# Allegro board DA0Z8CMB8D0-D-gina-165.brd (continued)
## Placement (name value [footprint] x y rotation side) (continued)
R462  ev@100/f_4  [RC0402]  57.79 157.32 270 bottom
R463  ev@100/f_4  [RC0402]  58.94 157.32 90 bottom
R464  *short_4  [SHORT0402]  149.95 156.83 0 bottom
R465  ev@1.33k/f_4  [RC0402]  31 156.68 180 bottom
R466  ev@243_4  [RC0402]  56.65 155.16 270 bottom
R467  22/j_4  [RC0402]  109.94 154.67 0 bottom
R468  ev@10k/f_4  [RC0402]  69.94 154.54 90 bottom
R469  ev@100/f_4  [RC0402]  67.32 154.52 270 bottom
R470  ev@100/f_4  [RC0402]  68.46 154.52 270 bottom
R471  ev@100/f_4  [RC0402]  64.4 153.89 0 bottom
R472  22/j_4  [RC0402]  109.94 153.65 0 bottom
R473  ev@100/f_4  [RC0402]  64.4 152.87 0 bottom
R474  2.2k_4  [RC0402]  87.33 152.64 90 bottom
R475  2.2k_4  [RC0402]  98 152.64 180 bottom
R476  *1m_4  [RC0402]  112.1 152.64 0 bottom
R477  ev@100/f_4  [RC0402]  66.05 152.24 270 bottom
R478  ev@100/f_4  [RC0402]  67.32 152.24 270 bottom
R479  ev@100/f_4  [RC0402]  68.46 152.24 270 bottom
R480  ev@100/f_4  [RC0402]  64.4 151.73 0 bottom
R481  2.2k_4  [RC0402]  98 151.62 180 bottom
R482  *1m_4  [RC0402]  112.1 151.62 0 bottom
R483  22/j_4  [RC0402]  109.94 150.61 0 bottom
R484  4.7k_4  [RC0402]  98 150.48 180 bottom
R485  ev@100/f_4  [RC0402]  64.4 150.46 0 bottom
R486  2.2k_4  [RC0402]  84.16 149.84 180 bottom
R487  ev@10k/f_4  [RC0402]  66.18 149.83 90 bottom
R488  22/j_4  [RC0402]  109.94 149.59 0 bottom
R489  10k_4  [RC0402]  98 149.34 180 bottom
R490  ev@100/f_4  [RC0402]  64.4 149.32 180 bottom
R491  100k_4  [RC0402]  143.47 149.08 180 bottom
R492  *short_4  [SHORT0402]  86.45 148.7 180 bottom
R493  ev@2.49k/f_4  [RC0402]  28.03 143.49 180 bottom
R494  *short_6  [SHORT0603]  152.36 139.81 180 bottom
R495  *0_8  [RC0805]  105.93 139.18 90 bottom
R497  *short0402  [SHORT0402]  102.07 137.78 180 bottom
R498  ev@243_4  [RC0402]  73.92 137.76 90 bottom
R499  10k_4  [RC0402]  101.81 136.64 180 bottom
R500  3.01k/f_4  [RC0402]  126.96 136.25 270 bottom
R501  1m_4  [RC0402]  129.63 135.72 180 bottom
R502  *0_4  [RC0402]  117.05 134.86 90 bottom
R503  *0_4  [RC0402]  118.07 134.86 90 bottom
R504  10k_4  [RC0402]  120.1 134.86 90 bottom
R505  10k_4  [RC0402]  121.12 134.86 90 bottom
R506  *10k_4  [RC0402]  104.35 134.48 270 bottom
R507  10k_4  [RC0402]  105.5 134.48 270 bottom
R508  10k_4  [RC0402]  101.86 134.35 0 bottom
R509  *short_4  [SHORT0402]  126.83 134.1 270 bottom
R510  3.01k/f_4  [RC0402]  127.85 134.1 270 bottom
R511  8.2k_4  [RC0402]  137.88 134.1 90 bottom
R512  *short_4  [SHORT0402]  138.9 134.1 90 bottom
R513  3.01k/f_4  [RC0402]  139.91 134.1 90 bottom
R514  2.2k_4  [RC0402]  141.94 134.1 90 bottom
R515  2.2k_4  [RC0402]  143.6 134.1 90 bottom
R516  *1k_4  [RC0402]  147.66 133.97 270 bottom
R517  *1k_4  [RC0402]  148.68 133.97 90 bottom
R518  *short0402  [SHORT0402]  97.75 133.71 270 bottom
R519  *0_4  [RC0402]  99.02 133.71 90 bottom
R520  10k_4  [RC0402]  150.17 133.59 270 bottom
R521  *0_4  [RC0402]  96.48 131.94 90 bottom
R522  100/f_4  [RC0402]  102.32 131.81 0 bottom
R523  10k_4  [RC0402]  148.17 131.56 270 bottom
R524  10k_4  [RC0402]  149.18 131.56 270 bottom
R525  10k_4  [RC0402]  150.2 131.56 270 bottom
R526  *short_4  [SHORT0402]  102.32 130.79 180 bottom
R527  10k_4  [RC0402]  148.68 129.9 180 bottom
R528  10k_4  [RC0402]  150.71 129.9 0 bottom
R529  10k_4  [RC0402]  152.74 129.9 180 bottom
R530  *short_4  [SHORT0402]  102.32 129.78 180 bottom
R531  *iv@10k_4  [RC0402]  152.74 128.89 180 bottom
R532  100/f_4  [RC0402]  102.32 128.76 0 bottom
R533  10k_4  [RC0402]  148.68 128.63 180 bottom
R534  *10k_4  [RC0402]  150.71 128.63 0 bottom
R535  *evg@10k_4  [RC0402]  152.74 127.62 0 bottom
R536  *10k_4  [RC0402]  148.68 126.86 0 bottom
R537  10k_4  [RC0402]  150.71 126.86 180 bottom
R538  10k_4  [RC0402]  154.52 126.86 90 bottom
R539  10k_4  [RC0402]  152.99 126.48 180 bottom
R540  *10k_4  [RC0402]  148.68 125.84 0 bottom
R541  10k_4  [RC0402]  150.71 125.84 180 bottom
R542  56_4  [RC0402]  102.32 125.46 180 bottom
R543  10k_4  [RC0402]  154.26 125.33 180 bottom
R544  *10k_4  [RC0402]  148.68 124.82 180 bottom
R545  10k_4  [RC0402]  150.71 124.82 180 bottom
R546  *62_4  [RC0402]  99.78 124.7 0 bottom
R547  10k_4  [RC0402]  152.61 124.7 90 bottom
R548  62_4  [RC0402]  102.32 124.32 180 bottom
R549  *10k_4  [RC0402]  155.41 124.19 0 bottom
R550  *short_4  [SHORT0402]  148.68 123.81 180 bottom
R551  10k_4  [RC0402]  150.71 123.81 180 bottom
R552  *ev@10k/f_4  [RC0402]  22.69 123.68 270 bottom
R553  ev@10k/f_4  [RC0402]  23.83 123.68 90 bottom
R554  130/f_4  [RC0402]  99.78 123.68 180 bottom
R555  *130/f_4  [RC0402]  102.32 123.17 180 bottom
R556  ev@100k_4  [RC0402]  152.99 123.17 0 bottom
R557  iv@10k_4  [RC0402]  157.06 122.79 180 bottom
R558  *short_4  [SHORT0402]  99.78 122.67 180 bottom
R559  10k_4  [RC0402]  148.68 122.67 180 bottom
R560  *10k_4  [RC0402]  155.03 122.79 180 bottom
R561  *10k_4  [RC0402]  150.71 122.54 0 bottom
R562  ev@243_4  [RC0402]  64.14 122.52 90 bottom
R563  ev@1.33k/f_4  [RC0402]  65.29 122.52 90 bottom
R564  ev@1.33k/f_4  [RC0402]  66.56 122.52 270 bottom
R565  43_4  [RC0402]  101.94 122.11 0 bottom
R566  *ev@10k/f_4  [RC0402]  22.69 121.52 270 bottom
R567  *ev@10k/f_4  [RC0402]  23.83 121.52 90 bottom
R568  *75_4  [RC0402]  99.78 121.52 180 bottom
R569  10k_4  [RC0402]  148.68 121.52 0 bottom
R570  10k_4  [RC0402]  150.88 121.52 0 bottom
R571  *1k_4  [RC0402]  156.8 121.27 270 bottom
R572  *short_4  [SHORT0402]  157.95 121.27 270 bottom
R573  *short_4  [SHORT0402]  159.22 121.27 90 bottom
R574  iv@1k_4  [RC0402]  153.76 121.52 180 bottom
R575  10k_4  [RC0402]  148.68 120.51 0 bottom
R576  10k_4  [RC0402]  150.71 120.51 180 bottom
R577  10k_4  [RC0402]  154.9 120.51 0 bottom
R578  75_4  [RC0402]  99.78 120.38 180 bottom
R579  *short_4  [SHORT0402]  101.84 120.23 180 bottom
R580  *1k_4  [RC0402]  148.68 119.49 0 bottom
R581  10k_4  [RC0402]  152.74 119.49 180 bottom
R582  10k_4  [RC0402]  154.77 119.49 180 bottom
R583  *ev@4.99k/f_4  [RC0402]  65.67 119.47 0 bottom
R584  *ev@10k/f_4  [RC0402]  67.7 119.47 180 bottom
R585  ev@4.99k/f_4  [RC0402]  69.86 119.47 180 bottom
R586  10k_4  [RC0402]  150.71 119.24 180 bottom
R587  ev@10k_4  [RC0402]  153.25 118.47 180 bottom
R588  iv@10k_4  [RC0402]  155.28 118.47 180 bottom
R589  ev@4.99k/f_4  [RC0402]  65.67 118.46 180 bottom
R590  ev@4.99k/f_4  [RC0402]  67.7 118.46 180 bottom
R591  *ev@4.99k/f_4  [RC0402]  69.86 118.46 0 bottom
R592  *100k_4  [RC0402]  148.68 118.22 180 bottom
R593  10k_4  [RC0402]  150.71 118.22 0 bottom
R594  *1k_4  [RC0402]  98.76 117.97 0 bottom
R595  *10k_4  [RC0402]  155.03 117.46 180 bottom
R596  10k_4  [RC0402]  150.71 117.08 0 bottom
R597  *short_4  [SHORT0402]  98.76 116.95 0 bottom
R598  *short_4  [SHORT0402]  148.68 116.95 180 bottom
R599  10k_4  [RC0402]  152.99 116.95 180 bottom
R600  *short_4  [SHORT0402]  155.03 116.32 180 bottom
R601  *short_4  [SHORT0402]  150.72 116.06 180 bottom
R602  *51_4  [RC0402]  98.76 115.93 180 bottom
R603  ev@10k/f_4  [RC0402]  44.28 115.43 180 bottom
R604  ev@40.2k/f_4  [RC0402]  42.25 114.92 270 bottom
R605  *ev@10k/f_4  [RC0402]  45.93 114.79 90 bottom
R606  *ev@10k/f_4  [RC0402]  47.08 114.79 90 bottom
R607  *ev@24.9k/f_4  [RC0402]  48.22 114.79 90 bottom
R608  *ev@10k/f_4  [RC0402]  49.36 114.79 90 bottom
R609  *ev@10k/f_4  [RC0402]  50.5 114.79 90 bottom
R610  *ev@10k/f_4  [RC0402]  51.65 114.79 90 bottom
R611  ev@2.2k_4  [RC0402]  53.93 114.79 90 bottom
R612  ev@2.2k_4  [RC0402]  55.08 114.79 90 bottom
R613  ev@10k/f_4  [RC0402]  56.22 114.79 90 bottom
R614  ev@2.2k_4  [RC0402]  57.36 114.79 270 bottom
R615  *0_4  [RC0402]  148.68 114.66 0 bottom
R616  *short_4  [SHORT0402]  150.71 114.56 0 bottom
R617  *short_4  [SHORT0402]  13.67 114.16 180 bottom
R618  *ev@30.1k/f_4  [RC0402]  44.28 114.16 0 bottom
R619  2.2k_4  [RC0402]  148.68 113.65 0 bottom
R620  *0_4  [RC0402]  150.71 113.55 180 bottom
R621  *short_4  [SHORT0402]  13.67 113.14 180 bottom
R622  2.2k_4  [RC0402]  154.39 113.14 0 bottom
R623  *ev@15k/f_4  [RC0402]  44.28 113.01 0 bottom
R624  ev@10k/f_4  [RC0402]  42.25 112.76 90 bottom
R625  *ev@4.99k/f_4  [RC0402]  45.93 112.63 90 bottom
R626  *ev@45.3k/f_4  [RC0402]  47.08 112.63 90 bottom
R627  ev@49.9k/f_4  [RC0402]  48.22 112.63 270 bottom
R628  *ev@45.3k/f_4  [RC0402]  49.36 112.63 90 bottom
R629  *ev@10k/f_4  [RC0402]  50.5 112.63 90 bottom
R630  *ev@10k/f_4  [RC0402]  51.65 112.63 90 bottom
R631  ev@2.2k_4  [RC0402]  53.93 112.63 90 bottom
R632  ev@2.2k_4  [RC0402]  55.08 112.63 90 bottom
R633  ev@2.2k_4  [RC0402]  56.22 112.63 270 bottom
R634  ev@10k/f_4  [RC0402]  57.36 112.63 90 bottom
R635  10k_4  [RC0402]  154.39 112.12 180 bottom
R636  10k_4  [RC0402]  154.39 110.6 270 bottom
R637  *10k_4  [RC0402]  155.41 110.6 270 bottom
R638  10k_4  [RC0402]  156.42 110.6 90 bottom
R639  200/f_4  [RC0402]  99.91 110.35 0 bottom
R640  100/f_4  [RC0402]  102.07 108.7 180 bottom
R641  *10k_4  [RC0402]  156.17 108.57 270 bottom
R642  10k_4  [RC0402]  157.18 108.57 90 bottom
R643  10k_4  [RC0402]  154.39 108.44 270 bottom
R644  *51_4  [RC0402]  102.07 107.43 180 bottom
R645  120/f_4  [RC0402]  100.54 107.17 270 bottom
R646  *10k_4  [RC0402]  154.01 106.92 0 bottom
R647  10k_4  [RC0402]  156.68 106.92 180 bottom
R648  10k_4  [RC0402]  151.22 106.66 0 bottom
R649  *short_4  [SHORT0402]  102.07 106.16 0 bottom
R650  *10k_4  [RC0402]  150.33 104.63 180 bottom
R651  10k_4  [RC0402]  152.49 104.63 180 bottom
R652  33_4  [RC0402]  142.33 104 0 bottom
R653  *0_4  [RC0402]  158.45 103.62 180 bottom
R654  49.9/f_4  [RC0402]  137.37 103.49 270 bottom
R655  10m_4  [RC0402]  150.96 102.98 90 bottom
R656  *0_4  [RC0402]  158.45 102.6 0 bottom
R657  33_4  [RC0402]  141.69 102.22 270 bottom
R658  *short_4  [SHORT0402]  142.71 102.22 270 bottom
R659  33_4  [RC0402]  143.72 102.22 270 bottom
R660  *330k_4  [RC0402]  144.74 102.22 90 bottom
R661  *0_4  [RC0402]  146.01 102.22 90 bottom
R662  *330k_4  [RC0402]  147.28 102.22 270 bottom
R663  10k_4  [RC0402]  148.29 102.22 90 bottom
R664  49.9/f_4  [RC0402]  137.5 101.96 180 bottom
R665  1m_4  [RC0402]  149.31 101.96 270 bottom
R666  *0_4  [RC0402]  158.45 101.58 180 bottom
R667  *0_4  [RC0402]  70.63 101.19 0 bottom
R668  100k_4  [RC0402]  66.13 100.82 90 bottom
R669  100k_4  [RC0402]  67.4 100.82 90 bottom
R670  *0_4  [RC0402]  53.68 100.69 90 bottom
R671  *short_4  [SHORT0402]  54.7 100.69 270 bottom
R672  *100k_4  [RC0402]  55.71 100.69 90 bottom
R673  *0_4  [RC0402]  153.76 100.57 0 bottom
R674  10k_4  [RC0402]  158.45 100.57 180 bottom
R675  *0_4  [RC0402]  70.63 100.18 0 bottom
R676  330k_4  [RC0402]  144.99 99.93 270 bottom
R677  330k_4  [RC0402]  147.02 99.93 90 bottom
R678  *short_4  [SHORT0402]  148.55 99.81 90 bottom
R679  *short_4  [SHORT0402]  149.69 99.81 270 bottom
R680  100k/f_4  [RC0402]  151.22 99.68 90 bottom
R681  *0_4  [RC0402]  152.23 99.68 90 bottom
R682  *short_4  [SHORT0402]  70.63 99.16 180 bottom
R683  *0_4  [RC0402]  153.88 98.92 0 bottom
R684  33_4  [RC0402]  140.8 98.15 270 bottom
R685  *short_4  [SHORT0402]  70.63 98.15 180 bottom
R686  *10k_4  [RC0402]  146.45 98.15 0 bottom
R687  *10k_4  [RC0402]  153.88 97.9 0 bottom
R688  10k_4  [RC0402]  146.45 97.13 0 bottom
R689  0_4  [RC0402]  149.56 96.88 90 bottom
R690  *short_4  [SHORT0402]  232.37 91.93 180 bottom
R691  *0_4  [RC0402]  213.06 91.3 180 bottom
R692  *short_4  [SHORT0402]  232.37 90.92 180 bottom
R693  *0_4  [RC0402]  213.06 90.28 180 bottom
R694  *0_4  [RC0402]  214.33 88.76 0 bottom
R695  *0_4  [RC0402]  216.62 88.63 180 bottom
R696  *0_4  [RC0402]  216.62 87.49 180 bottom
R697  10k_4  [RC0402]  180.76 84.21 180 bottom
R698  *short_8  [SHORT0805]  188.3 82.28 180 bottom
R699  10k_4  [RC0402]  185.38 82.15 0 bottom
R700  *10k_4  [RC0402]  214.21 81.64 90 bottom
R701  *short_4  [SHORT0402]  215.22 81.64 270 bottom
R702  *0_4  [RC0402]  216.24 81.64 90 bottom
R703  *0_4  [RC0402]  217.26 81.64 90 bottom
R704  0_4  [RC0402]  218.27 81.64 90 bottom
R705  1k_4  [RC0402]  185.38 80.88 0 bottom
R706  *0_4  [RC0402]  214.46 79.74 180 bottom
R707  0_4  [RC0402]  214.46 78.6 180 bottom
R708  *short_8  [SHORT0805]  38.82 74.41 90 bottom
R709  66.5/f_4  [RC0402]  132.52 72.5 0 bottom
R710  66.5/f_4  [RC0402]  134.81 72.5 180 bottom
R711  *short_4  [SHORT0402]  232.37 73.39 180 bottom
R712  *short_4  [SHORT0402]  232.37 72.37 180 bottom
R713  *short_8  [SHORT0805]  216.75 70.09 180 bottom
R716  *0_6  [RC0603]  151.09 67.04 0 bottom
R717  *0_6  [RC0603]  148.8 66.53 270 bottom
R718  *short_6  [SHORT0603]  151.08 65.83 0 bottom
R719  26.1/f_4  [RC0402]  64.47 65.64 180 bottom
R720  *10k_4  [RC0402]  153.25 65.64 90 bottom
R721  *0_6  [RC0603]  218.14 65.64 90 bottom
R722  20k/f_4  [RC0402]  129.73 65.52 270 top
R723  *short_6  [SHORT0603]  155.66 64.88 270 bottom
R724  0_4  [RC0402]  138.26 64.63 180 bottom
R725  26.1/f_4  [RC0402]  64.47 64.5 180 bottom
R726  20k/f_4  [RC0402]  128.53 64.07 270 top
R727  *short_4  [SHORT0402]  144.6 63.67 90 bottom
R728  *short_4  [SHORT0402]  145.74 63.67 90 bottom
R729  *short_4  [SHORT0402]  146.76 63.67 90 bottom
R730  *short_4  [SHORT0402]  147.78 63.67 90 bottom
R731  26.1/f_4  [RC0402]  64.47 63.36 180 bottom
R732  *0_4  [RC0402]  138.26 63.36 180 bottom
R733  *short_4  [SHORT0402]  148.79 63.29 90 bottom
R734  *short_4  [SHORT0402]  149.81 63.29 90 bottom
R735  *short_4  [SHORT0402]  151.08 63.29 90 bottom
R736  *short_4  [SHORT0402]  152.22 63.29 90 bottom
R737  *short_6  [SHORT0603]  155.15 62.98 0 bottom
R738  34.8/f_4  [RC0402]  62.19 62.47 180 bottom
R739  26.1/f_4  [RC0402]  64.47 62.34 180 bottom
R740  *0_4  [RC0402]  138.26 62.09 180 bottom
R741  *100k_4  [RC0402]  215.6 62.09 180 bottom
R742  34.8/f_4  [RC0402]  62.32 61.07 0 bottom
R743  34.8/f_4  [RC0402]  64.47 61.07 180 bottom
R744  34.8/f_4  [RC0402]  64.47 59.8 180 bottom
R745  240/f_4  [RC0402]  62.32 59.67 180 bottom
R746  34.8/f_4  [RC0402]  62.32 58.53 0 bottom
R747  34.8/f_4  [RC0402]  64.47 58.53 180 bottom
R748  *short_4  [SHORT0402]  223.99 57.77 0 bottom
R749  *gs@short_6  [SHORT0603]  220.05 57.64 0 bottom
R750  34.8/f_4  [RC0402]  62.32 57.39 0 bottom
R751  34.8/f_4  [RC0402]  64.47 57.39 180 bottom
R752  240/f_4  [RC0402]  96.22 56.75 180 bottom
R753  *short_4  [SHORT0402]  223.99 55.99 0 bottom
R754  *gs@4.7k_4  [RC0402]  220.3 55.36 180 bottom
R755  *gs@short_4  [SHORT0402]  220.3 54.34 180 bottom
R756  240/f_4  [RC0402]  80.28 54.33 180 bottom
R757  240/f_4  [RC0402]  112.61 53.83 270 bottom
R758  *short_4  [SHORT0402]  223.99 53.58 0 bottom
R759  *gs@short_4  [SHORT0402]  216.24 51.67 90 bottom
R760  *gs@4.7k_4  [RC0402]  217.38 51.67 90 bottom
R761  *gs@short_4  [SHORT0402]  218.4 51.67 90 bottom
R762  *short_4  [SHORT0402]  223.99 51.04 0 bottom
R763  *1k_4  [RC0402]  122.13 48.17 0 bottom
R764  *1k_4  [RC0402]  124.42 48.17 180 bottom
R765  *tpmi@0_4  [RC0402]  172.3 48.12 0 bottom
R766  *1k_4  [RC0402]  110.14 47.35 180 bottom
R767  tpm@0_4  [RC0402]  172.3 47.1 0 bottom
R768  *1k_4  [RC0402]  122.13 46.85 0 bottom
R769  *short_4  [SHORT0402]  160.36 46.72 0 bottom
R770  *1k_4  [RC0402]  110.14 46.08 180 bottom
R771  *1k_4  [RC0402]  122.18 45.58 180 bottom
R772  *0_4  [RC0402]  110.14 44.81 180 bottom
R773  *1k_4  [RC0402]  122.18 44.56 0 bottom
R774  *short_6  [SHORT0603]  239.61 44.56 0 bottom
R775  *20k/f_4  [RC0402]  172.3 44.05 180 bottom
R776  *0_4  [RC0402]  110.14 43.54 180 bottom
R777  *1k_4  [RC0402]  122.18 43.54 180 bottom
R778  *tpmi@4.7k  [RC0402]  172.3 43.04 0 bottom
R779  *short_4  [SHORT0402]  223.48 43.04 90 bottom
R780  *tpm@4.7k  [RC0402]  172.3 42.02 180 bottom
R781  tpm@10k_4  [RC0402]  172.3 41 0 bottom
R782  tpm@0_4  [RC0402]  160.36 40.75 0 bottom
R783  *short_4  [SHORT0402]  223.48 40.5 270 bottom
R784  *tpmi@0_4  [RC0402]  172.3 39.99 0 bottom
R785  *short_4  [SHORT0402]  160.36 39.73 0 bottom
R786  *short_4  [SHORT0402]  223.99 38.85 0 bottom
R787  tpmn@0_4  [RC0402]  160.36 38.72 0 bottom
R788  *short_4  [SHORT0402]  223.99 37.7 0 bottom
R789  *0_4  [RC0402]  235.29 26.4 0 bottom
R790  0_4  [RC0402]  224.62 88.76 270 top
R791  0_4  [RC0402]  225.64 88.76 270 top
R792  *100k_4  [RC0402]  224.49 64.75 0 bottom
R794  *68.1k/f_4  [RC0402]  80.37 74.25 180 top
R795  *4.7k_4  [RC0402]  83.27 73.24 180 top
R796  *150k/f_4  [RC0402]  80.37 75.29 0 top
R797  *4.7k_4  [RC0402]  80.37 73.24 180 top
RP1  *10k_10p8r  [10P8R]  62.44 48.75 90 top
RP2  10k_10p8r  [10P8R]  159.98 108.7 270 bottom
RV1  *5v/0.2p_4  [CC0402]  84.79 155.69 90 top
SW1  *power switch  [SW-TME-532-V-6P]  163.03 42.66 0 top
SW2  switch_1.5  [SW-TC901-AA1G-A160T-6P]  103.88 42.46 270 bottom
TP1  *  [TP2650]  104.1 164.07 0 top
TP2  *  [TP2650]  110.91 140.14 0 top
TP3  *  [TP2650]  112.18 140.14 0 top
TP4  *  [TP2650]  137.5 132.32 0 top
TP6  *  [TP2650]  137.75 130.79 0 top
TP9  *  [TP2650]  141.56 129.65 0 top
TP10  *  [TP2050]  49.39 129.4 270 top
TP11  *  [TP2050]  50.76 128.76 270 top
TP13  *  [TP2675]  52.16 127.75 270 top
TP14  *  [TP2650]  142.2 127.11 0 top
TP15  pad  [TP2650]  109.94 126.83 0 top
TP16  *  [TP2650]  106.77 126.35 0 top
TP17  *  [TP2650]  108.16 126.32 0 top
TP18  *  [TP2675]  50.12 126.22 270 top
TP19  *  [TP2650]  104.23 126.09 0 top
TP20  *  [TP2650]  105.5 126.09 0 top
TP21  *  [TP2650]  109.31 125.64 0 top
TP22  *  [TP2050]  52.92 124.82 0 top
TP23  *  [TP2650]  107.02 124.75 0 top
TP24  pad  [TP2650]  108.31 124.75 0 top
TP25  pad  [TP2650]  109.41 124.06 0 top
TP26  *  [TP2650]  146.06 124.06 0 top
TP27  pad  [TP2650]  106.59 123.43 0 top
TP28  *  [TP2650]  105.32 123.3 0 top
TP29  pad  [TP2650]  108.16 123.3 0 top
TP30  *  [TP2650]  104.1 122.95 0 top
TP31  pad  [TP2650]  109.33 122.59 0 top
TP32  *  [TP2650]  106.46 122.16 0 top
TP33  *  [TP2650]  103.59 121.78 0 top
TP34  pad  [TP2650]  108.16 121.78 0 top
TP35  *  [TP2650]  93.43 121.65 0 top
TP36  *  [TP2650]  150.53 122.34 0 top
TP37  pad  [TP2650]  109.31 121.09 0 top
TP38  *  [TP2650]  101.94 121.01 0 top
TP39  *  [TP2650]  146.52 121.52 0 top
TP40  *  [TP2650]  107.02 120.3 0 top
TP41  *  [TP2650]  108.31 120.25 0 top
TP42  *  [TP2650]  102.83 120 0 top
TP43  *  [TP2650]  145.91 120.38 0 top
TP44  *  [TP2650]  101.56 119.62 0 top
TP45  *  [TP2650]  100.16 119.49 0 top
TP46  *  [TP2650]  93.52 119.2 0 top
TP47  *  [TP2650]  106.66 118.96 0 top
TP48  *  [TP2650]  145.35 118.88 0 top
TP49  pad  [TP2650]  109.31 118.86 0 top
TP50  pad  [TP2650]  108.02 118.77 0 top
TP51  *  [TP2650]  146.74 118.02 0 top
TP52  *  [TP2650]  101.99 118.37 0 top
TP53  *  [TP2650]  104.86 118.35 0 top
TP54  pad  [TP2650]  98.59 117.79 0 top
TP55  *  [TP2650]  106.38 117.66 0 top
TP56  pad  [TP2650]  109.31 117.36 0 top
TP57  pad  [TP2650]  108.04 117.31 0 top
TP58  pad  [TP2650]  126.79 117.15 0 top
TP59  pad  [TP2650]  128.02 116.82 0 top
TP60  *  [TP2650]  146.14 116.7 0 top
TP61  *  [TP2650]  144.74 116.44 0 top
TP62  *  [TP2650]  98.56 116.21 0 top
TP63  *  [TP2650]  104.86 116.19 0 top
TP64  *  [TP2650]  99.91 116.06 0 top
TP65  *  [TP2650]  88.35 115.93 0 top
TP66  pad  [TP2650]  126.07 115.93 0 top
TP67  *  [TP2650]  139.91 115.93 0 top
TP68  *  [TP2650]  101.18 115.68 0 top
TP69  *  [TP2650]  94.45 115.43 0 top
TP70  *  [TP2650]  146.52 115.43 0 top
TP71  pad  [TP2650]  109.89 115.4 0 top
TP72  pad  [TP2650]  106.64 115.3 0 top
TP73  pad  [TP2650]  108.29 115.3 0 top
TP74  *  [TP2650]  144.61 115.17 0 top
TP75  pad  [TP2650]  107.43 114.28 0 top
TP76  *  [TP2650]  144.87 113.52 0 top
TP77  *  [TP2650]  146.39 113.52 0 top
TP78  *  [TP2650]  126.35 113.12 0 top
TP79  *  [TP2650]  143.21 112.73 0 top
TP80  *  [TP2650]  126.35 111.24 0 top
TP81  *  [TP2650]  146.21 106.59 0 top
TP82  *  [TP2650]  145.25 108.95 0 top
TP83  *  [TP2650]  143.21 108.82 0 top
TP84  *  [TP2650]  86.28 105.63 0 top
TP85  *  [TP2650]  35.39 102.98 0 top
TP86  *  [TP2650]  87 93.99 0 top
TP87  *  [TP2650]  84.46 89.16 0 top
TP88  *  [TP2650]  153.88 83.93 0 top
TP89  *  [TP2650]  155.15 83.93 0 top
TP90  *pad  [TP2650]  221.95 80.88 0 top
TP91  *pad  [TP2650]  225.26 80.76 0 top
TP92  *pad  [TP2650]  216.62 79.36 270 top
TP93  *pad  [TP2650]  216.62 78.09 270 top
TP94  *pad  [TP2650]  216.62 76.69 270 top
TP95  *  [TP2650]  158.71 67.17 0 top
TP96  *  [TP2650]  158.71 65.9 0 top
TP97  *  [TP2650]  137.25 56.17 0 top
TP98  *  [TP2650]  141.94 50.28 0 top
TP99  *  [TP2650]  157.82 44.56 0 top
TP100  *  [TP2650]  168.87 40.75 0 top
TP101  *  [TP2650]  240.12 34.4 0 top
TP102  *  [TP2650]  240.12 33 0 top
TP103  *pad  [TP2675]  96.48 155.56 180 bottom
TP104  *pad  [TP2675]  96.48 150.73 180 bottom
TP105  *pad  [TP2675]  105.37 147.43 180 bottom
TP106  *  [TP2650]  116.14 138.06 180 bottom
TP107  *  [TP2650]  117.43 138.03 180 bottom
TP108  *  [TP2650]  112.73 135.62 180 bottom
TP109  *  [TP2650]  114.13 135.62 180 bottom
TP110  pad  [TP2650]  145.3 135.37 180 bottom
TP111  pad  [TP2650]  146.64 135.37 180 bottom
TP112  pad  [TP2650]  103.34 134.98 180 bottom
TP113  *  [TP2650]  109.94 134.35 180 bottom
TP114  *  [TP2650]  111.21 134.22 180 bottom
TP115  pad  [TP2650]  102.32 133.08 180 bottom
TP116  *  [TP2650]  100.8 132.95 180 bottom
TP117  *  [TP2650]  100.54 126.88 180 bottom
TP118  *  [TP2650]  102.32 126.6 180 bottom
TP119  *  [TP2650]  100.85 125.64 180 bottom
TP120  *  [TP2050]  28.28 124.44 90 bottom
TP121  *  [TP2650]  87.46 123.17 180 bottom
TP122  *  [TP2050]  28.28 122.92 90 bottom
TP123  *  [TP2650]  152.33 121.57 180 bottom
TP124  *  [TP2050]  28.28 121.52 90 bottom
TP125  pad  [TP2650]  101.33 121.17 180 bottom
TP126  *  [TP2650]  153.12 120.51 180 bottom
TP127  *  [TP2050]  28.28 120.13 90 bottom
TP128  *  [TP2650]  103.08 119.39 180 bottom
TP129  *  [TP2650]  98.56 119.14 180 bottom
TP130  *  [TP2650]  23.53 119.03 180 bottom
TP131  *  [TP2650]  99.86 118.91 180 bottom
TP132  *  [TP2650]  101.96 118.4 180 bottom
TP133  *  [TP2650]  147.02 118.02 180 bottom
TP134  *  [TP2650]  156.45 117.46 180 bottom
TP135  *  [TP2650]  147.02 116.75 180 bottom
TP136  *  [TP2050]  45.73 116.6 90 bottom
TP137  *  [TP2050]  50.35 116.19 180 bottom
TP138  *  [TP2050]  51.62 116.19 180 bottom
TP139  *  [TP2650]  100.52 115.88 180 bottom
TP140  *  [TP2650]  146.9 115.48 180 bottom
TP141  *  [TP2650]  96.17 112.81 180 bottom
TP142  *  [TP2650]  148.7 112.58 180 bottom
TP143  *  [TP2650]  148.9 107.5 180 bottom
TP144  pad  [TP2650]  152.99 105.9 180 bottom
TP145  pad  [TP2650]  148.93 105.65 180 bottom
TP146  pad  [TP2650]  105.39 102.55 180 bottom
TP147  pad  [TP2650]  105.62 100.95 180 bottom
TP148  *  [TP2650]  218.14 87.36 180 bottom
TP149  *  [TP2650]  218.14 86.09 180 bottom
TP150  *  [TP2650]  217.64 76.82 180 bottom
TP151  *  [TP2650]  217.64 75.55 180 bottom
TP152  *  [TP2650]  217.64 74.28 180 bottom
TP153  *  [TP2650]  213.83 54.21 180 bottom
TP154  *  [TP2650]  161.12 48.62 180 bottom
TP155  *  [TP2650]  100.75 46.39 180 bottom
TP156  *  [TP2650]  109.43 41.31 180 bottom
TP157  *  [TP2650]  134.6 128.48 0 top
TP158  *  [TP2650]  126.81 130.29 0 top
TP159  *  [TP2650]  135.57 129.37 0 top
TP160  *  [TP2650]  126.48 131.89 0 top
U1  *uclamp2512t.tct  [ESD8-2X1-5]  150.58 166.35 270 top
U2  *rclamp0524p  [SLP10-2_5X1-5-10P]  106.38 163.69 0 top
U3  *rclamp0524p  [SLP10-2_5X1-5-10P]  110.96 163.69 0 top
U4  transformer  [TRF-LC401-8P]  145.88 162.54 180 top
U5  m74vhc1gt125df2g  [SSOP5-P-A-TOSHIBA-B]  99.4 161.91 180 top
U6  m74vhc1gt125df2g  [SSOP5-P-A-TOSHIBA-B]  99.4 158.99 180 top
U7  transformer  [TRF-LC401-8P]  145.25 157.97 180 top
U8  *uclamp2512t.tct  [ESD8-2X1-5]  152.61 157.72 90 top
U9  *uclamp2512t.tct  [ESD8-2X1-5]  134.58 157.59 0 top
U10  74aup1g07gw  [SOT353-1-2_125-65-5P]  129.24 155.81 0 top
U11  ev@vram _ddr3_hynix_256mx16  [BGA96-HYNIX-H5TQ1G63AFP]  38.2 153 90 top
U12  ev@vram _ddr3_hynix_256mx16  [BGA96-HYNIX-H5TQ1G63AFP]  50.07 153 90 top
U13  ev@vram _ddr3_hynix_256mx16  [BGA96-HYNIX-H5TQ1G63AFP]  64.73 141.55 0 top
U14  w25q64fw  -- 8mb  [SOIC8-8-1_27]  152.99 133.71 0 top
U15  *74aup1g07gw  [SOT353-1-2_125-65-5P]  82.76 129.9 90 top
U16  ev@vram _ddr3_hynix_256mx16  [BGA96-HYNIX-H5TQ1G63AFP]  64.73 129.68 0 top
U17  *74cbtlv3126  [VQFN14-3_5X3_5-5-15P]  93.81 125.08 90 top
U18  g524b2t11u  [SOT23-5]  11.26 118.86 270 top
U19  g524b2t11u  [SOT23-5]  240.24 110.47 90 top
U20  tc7sh08fu  [SSOP5-P-A-TOSHIBA-B]  160.04 108.31 90 top
U21  *ev@nl17sz32dft2g  [SSOP5-P-A-TOSHIBA-B]  40.34 105.27 0 top
U22  ev@mc74vhc1g08dft2g  [SSOP5-P-A-TOSHIBA-B]  39.13 102.33 180 top
U23  74aup1g07gw  [SOT353-1-2_125-65-5P]  98.76 92.95 0 top
U24  rtl8411ba-cg  [QFN64-9X9-5-65P-RTL8411]  215.73 85.96 180 top
U25  slg55584a  [TDFN8-2X2-5-9P-MAX14566]  225.51 69.07 90 top
U26  tc7sh08fu  [SSOP5-P-A-TOSHIBA-B]  229.7 65.01 0 top
U27  *tc7sh08fu  [SSOP5-P-A-TOSHIBA-B]  132.7 64.75 270 top
U28  ram _ddr3l  [BGA96-ELPIDA-EDJ4216EBBG-DJ-F]  72.16 63.73 0 top
U29  ram _ddr3l  [BGA96-ELPIDA-EDJ4216EBBG-DJ-F]  85.36 63.73 0 top
U30  ram _ddr3l  [BGA96-ELPIDA-EDJ4216EBBG-DJ-F]  104.16 63.73 0 top
U31  ram _ddr3l  [BGA96-ELPIDA-EDJ4216EBBG-DJ-F]  117.37 63.73 0 top
U32  it8587e/fx  [LQFP128-16X16-4-1_6H]  148.04 59.93 270 top
U33  *g923-330t1uf  [SOT23-5]  241.51 51.93 90 top
U34  alc3225  [QFN48-6X6-4-49P-ALC280]  234.78 40.12 270 top
U35  transformer  [TRF-LC401-8P]  145.88 162.54 180 bottom
U36  transformer  [TRF-LC401-8P]  145.25 157.97 180 bottom
U37  *uclamp2512t.tct  [ESD8-2X1-5]  134.96 157.08 90 bottom
U38  ev@vram _ddr3_hynix_256mx16  [BGA96-HYNIX-H5TQ1G63AFP]  38.2 153 90 bottom
U39  ev@vram _ddr3_hynix_256mx16  [BGA96-HYNIX-H5TQ1G63AFP]  50.07 153 90 bottom
U40  it6513n-qfn-48  [QFN48-6X6-4-49P-IT6513FN]  103.97 152.26 0 bottom
U41  ev@vram _ddr3_hynix_256mx16  [BGA96-HYNIX-H5TQ1G63AFP]  64.73 141.55 0 bottom
U42  74aup1g07gw  [SOT353-1-2_125-65-5P]  98.76 136 180 bottom
U43  n15s-gt  [BGA595-NVIDIA-N13P-GV2-S-A2]  43 130.76 90 bottom
U44  ev@vram _ddr3_hynix_256mx16  [BGA96-HYNIX-H5TQ1G63AFP]  64.73 129.68 0 bottom
U45  hsw_ult_ddr3l/bga  [BGA1168-INTEL-HASWELL]  125.51 118.76 0 bottom
U46  g5243at11u  [SOT23-2_8-95-6P]  44.41 105.77 270 bottom
U47  tc7sh08fu  [SSOP5-P-A-TOSHIBA-B]  157.06 98.54 0 bottom
U48  g524b2t11u  [SOT23-5]  232.62 81.01 90 bottom
U49  g524a1t11u  [SOT23-5-2_8-95-5P-G708]  227.97 65.26 0 bottom
U50  ram _ddr3l  [BGA96-ELPIDA-EDJ4216EBBG-DJ-F]  72.16 63.73 180 bottom
U51  ram _ddr3l  [BGA96-ELPIDA-EDJ4216EBBG-DJ-F]  85.36 63.73 180 bottom
U52  ram _ddr3  [BGA96-ELPIDA-EDJ4216EBBG-DJ-F]  104.16 63.73 180 bottom
U53  ram _ddr3l  [BGA96-ELPIDA-EDJ4216EBBG-DJ-F]  117.37 63.73 180 bottom
U54  gs@lis3dhtr  [SENSOR-3X3-5-16P-SMT]  216.57 55.36 180 bottom
U55  *m24c02-wmn6tp  [SOIC8-6-1_27]  116.16 45.45 270 bottom
U56  tpm@npct650aa0wx_tssop28  [TSSOP28-6_4-65-SLB9635TT]  166.2 43.04 270 bottom
Y1  25mhz_xtal  [XTL-3_2X2_5-2_2X1_6]  225.89 94.47 0 top
Y2  *27mhz  [XTL-3_2X2_5-2_2X1_6]  101.81 144.64 180 bottom
Y3  24mhz  [XTL-3_2X2_5-2_2X1_6]  129.63 137.91 180 bottom
Y4  ev@27mhz +-10ppm  [XTL-3_2X2_5-2_2X1_7]  61.3 118.6 180 bottom
Y5  32.768khz  [XTL-3_2X1_5-2_5-0_8H]  155.41 103.23 270 bottom

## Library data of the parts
C1-C14 C17-C20 C23-C54 C56-C58 C61-C72 C74-C77 C79 C81-C83 C85 C86 C98 C101 C102 C107 C109 C110 C116 C120-C123 C128-C130 C132-C134 C138 C141 C143-C145 C147 C148 C150 C152 C153 C156-C158 C160 C161 C163-C173 C175 C178 C186 C189-C194 C197-C205 C208 C209 C212 C216 C225-C227 C229 C231 C233 C236-C239 C249-C256 C259 C261-C267 C273-C275 C277-C285 C287-C290 C294-C305 C308 C309 C311 C314 C315 C317 C321 C323 C324 C326-C332 C334-C336 C338 C342 C343 C345 C347 C351 C353-C359 C361 C362 C364-C366 C368-C373 C375-C417 C419-C424 C427-C430 C432-C460 C466 C467 C470 C472-C476 C478 C481 C483 C487-C489 C491-C493 C495 C498 C500 C502 C503 C506 C509 C512-C514 C516-C527 C529 C531-C539 C543-C545 C547-C570 C573-C575 C577-C584 C587 C588 C590 C592-C594 C596-C601 C603 C609 C610 C612-C617 C620 C622-C639 C641 C642 C645-C653 C655-C660 C662 C664-C690 C692-C704 C707-C713 C715-C721 C723-C736 C738-C755 C757-C759 C761-C772 C775-C779 C781 D3 D4 D6-D13 D21-D27 D29-D32 D35 PC1-PC4 PC6 PC7 PC9-PC13 PC18-PC20 PC23 PC35 PC38 PC39 PC41 PC44-PC47 PC49 PC59 PC62 PC64 PC67-PC69 PC72 PC79 PC81 PC82 PC84 PC85 PC87 PC88 PC90 PC91 PC94-PC96 PC101 PC104 PC116 PC119 PC124 PC130-PC133 PC140 PC142 PC143 PC147 RV1 = CC0402
C15 C16 C21 C22 C55 C73 C78 C80 C84 C88 C89 C91 C92 C97 C105 C106 C108 C111-C115 C118 C124-C126 C131 C135-C137 C139 C140 C142 C149 C151 C154 C155 C159 C162 C174 C187 C188 C195 C196 C206 C207 C211 C213-C215 C217 C218 C230 C234 C240-C245 C248 C257 C268-C272 C276 C293 C307 C310 C312 C313 C316 C318-C320 C322 C325 C333 C337 C339 C341 C344 C346 C348-C350 C352 C360 C363 C367 C374 C418 C425 C426 C431 C461-C465 C468 C469 C471 C477 C479 C480 C482 C484-C486 C490 C494 C496 C497 C499 C501 C504 C505 C507 C508 C510 C511 C515 C530 C540-C542 C546 C571 C576 C585 C589 C591 C604 C608 C611 C621 C640 C643 C644 C654 C663 C705 C714 C722 C737 C756 C760 C773 C774 PC5 PC8 PC14 PC15 PC17 PC21 PC22 PC24-PC27 PC30-PC32 PC36 PC37 PC40 PC42 PC43 PC48 PC51-PC58 PC60 PC61 PC63 PC65 PC66 PC70 PC71 PC73-PC78 PC83 PC93 PC100 PC102 PC103 PC107 PC113 PC118 PC120 PC121 PC123 PC125 PC128 PC129 PC135 PC138 PC141 PC145 PC148-PC150 = CC0603
C59 C60 C87 C90 C93-C96 C99 C100 C103 C104 C119 C176 C177 C179-C185 C210 C219-C224 C228 C232 C235 C246 C247 C258 C260 C286 C292 C586 C595 C602 C605-C607 C618 C619 C661 PC16 PC33 PC34 PC50 PC86 PC89 PC92 PC98 PC106 PC108 PC109 PC111 PC112 PC115 PC117 PC122 PC126 PC139 = CC0805
C117 L13 L15 L31 PR10 PR29 PR41 PR42 PR50 PR53 PR56 PR83 PR91-PR93 PR105 PR106 PR108 PR109 PR121 PR122 PR124 PR125 PR132-PR134 PR152 PR161 PR164 PR205 PR206 R67 R109 R154 R194 R212 R230 R262-R264 R279 R322 R332 R337 R363 R428-R431 R716 R717 R721 = RC0603
C127 C691 C706 PC134 PC137 = CC1206
C146 C340 = CC3528
C291 C306 C572 PC28 PC29 PC80 PC97 PC99 = CC7343
C528 = CC1808
CN1 = RJ45-JM361C-HP34AA03-9H-8P
CN2 = HDMI-C12826-11905-L-19P-SMT
CN3 = DSUB-10296-00021-15P
CN4 CN10 CN20 = 50224-00401-001-4P-L
CN5 = UB2-C14793-10409-L-4P-R
CN6 = 50501-0120N-001-12P-L
CN7 = GS12401-1011-9H-40P-R
CN8 CN13 = UB3-50928-0090A-001-9P
CN9 = BAT-23_2-4_2
CN11 = SATA-51205-0134T-001-13P-R
CN12 = NGFF-APCI0076-P001A-75P-KE
CN14 = 88511-180N-18P-L
CN15 = 51596-02601-001-26P-L
CN16 = 50503-0040N-V01-4P-L
CN17 = 196479-06041-3-6P-L
CN18 = 88502-06XX-6P-L-SMT
CN19 = CARD-CS1R-111-H-N-11P
CN21 = PHJK-2SJ3052-005111F-7P
CN22 = 50281-0040N-001-4P-L
CP1-CP6 = 8P4R
D1 = CC1812
D2 D5 D14 D17-D20 D28 D33 D34 D36-D38 PD1 PD3-PD5 PD8 = DSM
D15 PQ1-PQ3 PQ5-PQ8 PQ14-PQ16 PQ18-PQ21 PQ24 PQ25 PQ27-PQ29 PQ33-PQ36 PQ42 PQ43 PQ45 PQ47 PQ54 Q1-Q4 Q6 Q8-Q11 Q13-Q15 Q17 Q23-Q26 Q28-Q30 Q32 Q33 Q35-Q41 = SOT23_213-3_3-2
D16 = DSMV
HOLE1-HOLE3 = H-C150D150N
HOLE4 = H-C236D157P2
HOLE5 = HG-ZRQ-1
HOLE6 HOLE9 HOLE17 HOLE21 = HG-C276D118P2
HOLE7 HOLE8 HOLE10 HOLE13 HOLE14 HOLE16 HOLE20 = HG-C236D118P2
HOLE11 = O-Z8C-1
HOLE12 = H-C217D138P2
HOLE15 = H-C197D138P2
HOLE18 = H-C236D165P2
HOLE19 = H-TC197BC142D142P2
J2 = JOPEN25X30_S
JDIM1 = DDR-DS1SK-20401-STD-204P-SMT
L2-L4 L8 L9 L14 L18-L20 L25 L27-L29 PR1-PR3 PR6 PR7 PR9 PR12 PR14-PR20 PR22 PR24-PR27 PR31-PR33 PR35 PR36 PR38 PR39 PR43 PR45-PR47 PR49 PR51 PR52 PR55 PR58-PR68 PR70 PR72 PR75-PR78 PR80-PR82 PR85 PR87-PR89 PR94-PR102 PR104 PR110 PR112-PR116 PR118 PR119 PR126-PR129 PR131 PR136 PR137 PR139-PR151 PR153-PR155 PR157-PR159 PR163 PR165-PR173 PR176-PR178 PR180-PR184 PR186 PR187 PR189-PR191 PR193-PR196 PR203 PR211 PR213-PR215 PR217 R3-R13 R15-R26 R28 R30-R56 R58-R66 R68-R71 R74-R78 R80 R83 R86-R108 R110-R112 R114-R116 R118-R123 R125 R126 R129-R132 R134-R143 R146-R153 R155-R161 R163 R164 R166 R167 R169-R180 R182 R184 R185 R187-R193 R196-R198 R201-R204 R206-R209 R213-R216 R219-R228 R231 R233-R235 R237 R238 R240-R248 R250-R252 R254 R255 R257-R260 R265-R267 R269-R272 R274 R275 R277 R280 R282-R285 R287-R290 R293 R295 R297-R301 R303 R304 R306 R308-R310 R312-R315 R318 R323 R325 R327-R331 R333-R336 R338-R348 R350 R351 R353-R357 R359-R362 R364-R375 R378-R381 R386-R388 R390 R391 R394 R397 R399-R407 R409-R413 R418-R421 R424 R425 R432 R433 R435 R436 R439-R459 R461-R463 R465-R491 R493 R498-R508 R510 R511 R513-R517 R519-R525 R527-R529 R531-R549 R551-R557 R559-R571 R574-R578 R580-R596 R599 R602-R615 R618-R620 R622-R648 R650-R657 R659-R670 R672-R677 R680 R681 R683 R684 R686-R689 R691 R693-R697 R699 R700 R702-R707 R709 R710 R719 R720 R722 R724-R726 R731 R732 R738-R747 R750-R752 R754 R756 R757 R760 R763-R768 R770-R773 R775-R778 R780-R782 R784 R787 R789-R792 R794-R797 = RC0402
L5 L7 L23 L26 = CHOKE-WCM2012-4P
L10-L12 L16 L21 L30 PR23 PR40 PR79 PR84 PR107 PR117 PR120 PR123 PR160 PR162 R324 R495 = RC0805
L17 = L2_5X1_8-1_8-SMT
L32 PR30 PR48 PR71 PR86 PR156 PR198 PR201 PR204 PR210 PR216 R79 R84 R113 R145 R168 R186 R200 R205 R210 R211 R253 R268 R273 R278 R286 R292 R305 R319 R320 R349 R358 R392 R393 R395 R398 R408 R422 R423 R426 R494 R718 R723 R737 R749 R774 = SHORT0603
LED1 LED2 = LED19-123-Y2ST1D-C30-2T-4P
PAD1 = SPAD-E858X1268
PC105 PC110 PC114 PC127 PC136 PC144 PC146 = ECAP6_3X6_1-7_2
PD2 = POWER-6_5-1_84-3P
PD6 PD7 PQ23 PQ26 PQ37 Q5 Q7 Q16 Q27 Q31 Q34 Q42 = UMT_213-3-1_3
PD9 = D-DO-214AC
PJ1 = 20288-04XX-4P-L
PJ2 = 50458-00801-V02-8P-L
PL1 = CHOKE-PCMC063T-R82MN-4P-SMT
PL2 PL5-PL10 = CHOKE-PCMC063T-3R3MN-SMT
PL3 PL4 = CHOKE-ETQP4LR36WFC-4P
PQ4 PQ17 PQ30-PQ32 PQ41 PQ44 PQ46 PQ48-PQ51 PQ53 PQ55 = WDFN5-3_05X3_05-65
PQ9 PQ10 PQ12 PQ22 PQ38-PQ40 = SO-8FL-5P-OA
PQ11 = IMD
PQ13 Q12 Q18-Q22 = SC70-2_1-65-6P
PQ52 = POWER-5X6-1_27-7P
PR4 PR5 PR8 PR11 PR13 PR28 PR34 PR37 PR44 PR54 PR57 PR74 PR90 PR103 PR111 PR130 PR138 PR174 PR175 PR179 PR185 PR188 PR192 PR197 PR199 PR200 PR202 PR208 PR209 PR212 PR218 R1 R2 R14 R27 R29 R57 R72 R73 R81 R82 R85 R124 R127 R162 R181 R183 R195 R199 R217 R218 R236 R239 R249 R256 R261 R276 R281 R291 R294 R296 R302 R307 R311 R316 R317 R321 R326 R352 R376 R377 R382-R385 R389 R396 R414-R417 R427 R434 R438 R460 R464 R492 R497 R509 R512 R518 R526 R530 R550 R558 R572 R573 R579 R597 R598 R600 R601 R616 R617 R621 R649 R658 R671 R678 R679 R682 R685 R690 R692 R701 R711 R712 R727-R730 R733-R736 R748 R753 R755 R758 R759 R761 R762 R769 R779 R783 R785 R786 R788 = SHORT0402
PR21 PR135 R117 R128 R133 R144 R165 R229 R232 R437 R698 R708 R713 = SHORT0805
PR69 PR207 = RC3216
PR73 = RC1206
PU1 = QFN32-4X4-4-42P-1H
PU2 PU4 = SON10-3X3-5-16P
PU3 = QFN24-4X4-5-25P
PU5 PU6 = QFN20-3X3-4-26P
PU7 = SON8-4_5X3_5-5-9P-SMT
PU8 U55 = SOIC8-6-1_27
PU9 = PVQFN20-3_5X3_5-5-25P
PU10 = QFN16-3X3-5-22P
RP1 RP2 = 10P8R
SW1 = SW-TME-532-V-6P
SW2 = SW-TC901-AA1G-A160T-6P
TP1-TP4 TP6 TP9 TP14-TP17 TP19-TP21 TP23-TP102 TP106-TP119 TP121 TP123 TP125 TP126 TP128-TP135 TP139-TP160 = TP2650
TP10 TP11 TP22 TP120 TP122 TP124 TP127 TP136-TP138 = TP2050
TP13 TP18 TP103-TP105 = TP2675
U1 U8 U9 U37 = ESD8-2X1-5
U2 U3 = SLP10-2_5X1-5-10P
U4 U7 U35 U36 = TRF-LC401-8P
U5 U6 U20-U22 U26 U27 U47 = SSOP5-P-A-TOSHIBA-B
U10 U15 U23 U42 = SOT353-1-2_125-65-5P
U11-U13 U16 U38 U39 U41 U44 = BGA96-HYNIX-H5TQ1G63AFP
U14 = SOIC8-8-1_27
U17 = VQFN14-3_5X3_5-5-15P
U18 U19 U33 U48 = SOT23-5
U24 = QFN64-9X9-5-65P-RTL8411
U25 = TDFN8-2X2-5-9P-MAX14566
U28-U31 U50-U53 = BGA96-ELPIDA-EDJ4216EBBG-DJ-F
U32 = LQFP128-16X16-4-1_6H
U34 = QFN48-6X6-4-49P-ALC280
U40 = QFN48-6X6-4-49P-IT6513FN
U43 = BGA595-NVIDIA-N13P-GV2-S-A2
U45 = BGA1168-INTEL-HASWELL
U46 = SOT23-2_8-95-6P
U49 = SOT23-5-2_8-95-5P-G708
U54 = SENSOR-3X3-5-16P-SMT
U56 = TSSOP28-6_4-65-SLB9635TT
Y1-Y3 = XTL-3_2X2_5-2_2X1_6
Y4 = XTL-3_2X2_5-2_2X1_7
Y5 = XTL-3_2X1_5-2_5-0_8H

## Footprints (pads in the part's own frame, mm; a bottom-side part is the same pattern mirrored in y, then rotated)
8P4R
  rect 0.406x1.092 smd: 1(-1.194,-0.8) 2(-1.194,0.8) 3(-0.406,-0.8) 4(-0.406,0.8) 5(0.406,-0.8) 6(0.406,0.8) 7(1.194,-0.8) 8(1.194,0.8)
10P8R
  rect 0.305x1.092 smd: 1(-1.27,-0.85) 2(-0.635,-0.85) 3(0,-0.85) 4(0.635,-0.85) 5(1.27,-0.85) 6(1.27,0.85) 7(0.635,0.85) 8(0,0.85) 9(-0.635,0.85) 10(-1.27,0.85)
20288-04XX-4P-L
  round 1.295 hole 0.889: 1(-3.75,0) 2(-1.25,0) 3(1.25,0) 4(3.75,0)
50224-00401-001-4P-L
  rect 0.61x1.549 smd: 1(-1.5,2) 2(-0.5,2) 3(0.5,2) 4(1.5,2)
  rect 1.194x1.803 smd: 5(-2.8,-1.875) 6(2.8,-1.875)
50281-0040N-001-4P-L
  rect 0.787x2.007 smd: 1(-1.875,4.05) 2(-0.625,4.05) 3(0.625,4.05) 4(1.875,4.05)
  rect 2.007x2.489 smd: 5(-4.075,0) 6(4.075,0)
50458-00801-V02-8P-L
  rect 0.559x1.295 smd: 1(-7,5.025) 2(-5,5.025) 3(-3,5.025) 4(-1,5.025) 5(1,5.025) 6(3,5.025) 7(5,5.025) 8(7,5.025)
  rect 1.295x2.057 smd: 9(-10.1,0) 10(10.1,0)
50501-0120N-001-12P-L
  rect 0.305x1.295 smd: 1(-2.75,2.8) 2(-2.25,2.8) 3(-1.75,2.8) 4(-1.25,2.8) 5(-0.75,2.8) 6(-0.25,2.8) 7(0.25,2.8) 8(0.75,2.8) 9(1.25,2.8) 10(1.75,2.8) 11(2.25,2.8) 12(2.75,2.8)
  rect 1.803x1.397 smd: 13(-4.4,0) 14(4.4,0)
50503-0040N-V01-4P-L
  rect 0.508x1.295 smd: 1(-1.5,2.8) 2(-0.5,2.8) 3(0.5,2.8) 4(1.5,2.8)
  rect 1.803x1.397 smd: 5(-3.65,0) 6(3.65,0)
51596-02601-001-26P-L
  rect 0.508x1.092 smd: 1(-10,1.55) 2(-9.2,1.55) 3(-8.4,1.55) 4(-7.6,1.55) 5(-6.8,1.55) 6(-6,1.55) 7(-5.2,1.55) 8(-4.4,1.55) 9(-3.6,1.55) 10(-2.8,1.55) 11(-2,1.55) 12(-1.2,1.55) 13(-0.4,1.55) 14(0.4,1.55) 15(1.2,1.55) 16(2,1.55) 17(2.8,1.55) 18(3.6,1.55) 19(4.4,1.55) 20(5.2,1.55) 21(6,1.55) 22(6.8,1.55) 23(7.6,1.55) 24(8.4,1.55) 25(9.2,1.55) 26(10,1.55)
  rect 1.651x1.295 smd: 27(-12.025,-0.2) 28(12.025,-0.2)
88502-06XX-6P-L-SMT
  rect 0.61x1.295 smd: 1(-2.5,2.65) 2(-1.5,2.65) 3(-0.5,2.65) 4(0.5,2.65) 5(1.5,2.65) 6(2.5,2.65)
  rect 2.057x1.905 smd: 7(-4.775,-0.25) 8(4.775,-0.25)
88511-180N-18P-L
  rect 0.305x1.295 smd: 1(-4.25,2.8) 2(-3.75,2.8) 3(-3.25,2.8) 4(-2.75,2.8) 5(-2.25,2.8) 6(-1.75,2.8) 7(-1.25,2.8) 8(-0.75,2.8) 9(-0.25,2.8) 10(0.25,2.8) 11(0.75,2.8) 12(1.25,2.8) 13(1.75,2.8) 14(2.25,2.8) 15(2.75,2.8) 16(3.25,2.8) 17(3.75,2.8) 18(4.25,2.8)
  rect 1.803x1.397 smd: 19(-5.9,0) 20(5.9,0)
196479-06041-3-6P-L
  rect 0.305x0.889 smd: 1(-1.25,2.7) 2(-0.75,2.7) 3(-0.25,2.7) 4(0.25,2.7) 5(0.75,2.7) 6(1.25,2.7)
  rect 1.092x1.803 smd: 7(-3.4,0) 8(3.4,0)
BAT-23_2-4_2
  round 0.787 hole 0.787 unplated: (0,-8)
  round 1.194 hole 1.194 unplated: (0,8)
  rect 2.007x3.988 smd: 1(14.5,0) 2(-15.8,0)
BGA96-ELPIDA-EDJ4216EBBG-DJ-F
  round 0.356 smd: A1(-3.2,6) A2(-2.4,6) A3(-1.6,6) A7(1.6,6) A8(2.4,6) A9(3.2,6) B1(-3.2,5.2) B2(-2.4,5.2) B3(-1.6,5.2) B7(1.6,5.2) B8(2.4,5.2) B9(3.2,5.2) C1(-3.2,4.4) C2(-2.4,4.4) C3(-1.6,4.4) C7(1.6,4.4) C8(2.4,4.4) C9(3.2,4.4) D1(-3.2,3.6) D2(-2.4,3.6) D3(-1.6,3.6) D7(1.6,3.6) D8(2.4,3.6) D9(3.2,3.6) E1(-3.2,2.8) E2(-2.4,2.8) E3(-1.6,2.8) E7(1.6,2.8) E8(2.4,2.8) E9(3.2,2.8) F1(-3.2,2) F2(-2.4,2) F3(-1.6,2) F7(1.6,2) F8(2.4,2) F9(3.2,2) G1(-3.2,1.2) G2(-2.4,1.2) G3(-1.6,1.2) G7(1.6,1.2) G8(2.4,1.2) G9(3.2,1.2) H1(-3.2,0.4) H2(-2.4,0.4) H3(-1.6,0.4) H7(1.6,0.4) H8(2.4,0.4) H9(3.2,0.4) J1(-3.2,-0.4) J2(-2.4,-0.4) J3(-1.6,-0.4) J7(1.6,-0.4) J8(2.4,-0.4) J9(3.2,-0.4) K1(-3.2,-1.2) K2(-2.4,-1.2) K3(-1.6,-1.2) K7(1.6,-1.2) K8(2.4,-1.2) K9(3.2,-1.2) L1(-3.2,-2) L2(-2.4,-2) L3(-1.6,-2) L7(1.6,-2) L8(2.4,-2) L9(3.2,-2) M1(-3.2,-2.8) M2(-2.4,-2.8) M3(-1.6,-2.8) M7(1.6,-2.8) M8(2.4,-2.8) M9(3.2,-2.8) N1(-3.2,-3.6) N2(-2.4,-3.6) N3(-1.6,-3.6) N7(1.6,-3.6) N8(2.4,-3.6) N9(3.2,-3.6) P1(-3.2,-4.4) P2(-2.4,-4.4) P3(-1.6,-4.4) P7(1.6,-4.4) P8(2.4,-4.4) P9(3.2,-4.4) R1(-3.2,-5.2) R2(-2.4,-5.2) R3(-1.6,-5.2) R7(1.6,-5.2) R8(2.4,-5.2) R9(3.2,-5.2) T1(-3.2,-6) T2(-2.4,-6) T3(-1.6,-6) T7(1.6,-6) T8(2.4,-6) T9(3.2,-6)
BGA96-HYNIX-H5TQ1G63AFP
  round 0.356 smd: A1(-6,-3.2) A2(-6,-2.4) A3(-6,-1.6) A7(-6,1.6) A8(-6,2.4) A9(-6,3.2) B1(-5.2,-3.2) B2(-5.2,-2.4) B3(-5.2,-1.6) B7(-5.2,1.6) B8(-5.2,2.4) B9(-5.2,3.2) C1(-4.4,-3.2) C2(-4.4,-2.4) C3(-4.4,-1.6) C7(-4.4,1.6) C8(-4.4,2.4) C9(-4.4,3.2) D1(-3.6,-3.2) D2(-3.6,-2.4) D3(-3.6,-1.6) D7(-3.6,1.6) D8(-3.6,2.4) D9(-3.6,3.2) E1(-2.8,-3.2) E2(-2.8,-2.4) E3(-2.8,-1.6) E7(-2.8,1.6) E8(-2.8,2.4) E9(-2.8,3.2) F1(-2,-3.2) F2(-2,-2.4) F3(-2,-1.6) F7(-2,1.6) F8(-2,2.4) F9(-2,3.2) G1(-1.2,-3.2) G2(-1.2,-2.4) G3(-1.2,-1.6) G7(-1.2,1.6) G8(-1.2,2.4) G9(-1.2,3.2) H1(-0.4,-3.2) H2(-0.4,-2.4) H3(-0.4,-1.6) H7(-0.4,1.6) H8(-0.4,2.4) H9(-0.4,3.2) J1(0.4,-3.2) J2(0.4,-2.4) J3(0.4,-1.6) J7(0.4,1.6) J8(0.4,2.4) J9(0.4,3.2) K1(1.2,-3.2) K2(1.2,-2.4) K3(1.2,-1.6) K7(1.2,1.6) K8(1.2,2.4) K9(1.2,3.2) L1(2,-3.2) L2(2,-2.4) L3(2,-1.6) L7(2,1.6) L8(2,2.4) L9(2,3.2) M1(2.8,-3.2) M2(2.8,-2.4) M3(2.8,-1.6) M7(2.8,1.6) M8(2.8,2.4) M9(2.8,3.2) N1(3.6,-3.2) N2(3.6,-2.4) N3(3.6,-1.6) N7(3.6,1.6) N8(3.6,2.4) N9(3.6,3.2) P1(4.4,-3.2) P2(4.4,-2.4) P3(4.4,-1.6) P7(4.4,1.6) P8(4.4,2.4) P9(4.4,3.2) R1(5.2,-3.2) R2(5.2,-2.4) R3(5.2,-1.6) R7(5.2,1.6) R8(5.2,2.4) R9(5.2,3.2) T1(6,-3.2) T2(6,-2.4) T3(6,-1.6) T7(6,1.6) T8(6,2.4) T9(6,3.2)
BGA595-NVIDIA-N13P-GV2-S-A2
  round 0.381 smd: A2(-9.9,10.7) A3(-9.1,10.7) A4(-8.3,10.7) A6(-6.6,10.7) A7(-5.8,10.7) A9(-4.12,10.7) A10(-3.32,10.7) A12(-1.64,10.7) A13(-0.84,10.7) A15(0.84,10.7) A16(1.64,10.7) A18(3.32,10.7) A19(4.12,10.7) A21(5.8,10.7) A22(6.6,10.7) A24(8.3,10.7) A25(9.1,10.7) A26(9.9,10.7) AA1(-10.7,-5.8) AA2(-9.9,-5.8) AA3(-9.1,-5.8) AA4(-8.3,-5.8) AA5(-7.5,-5.8) AA6(-6.66,-5.8) AA7(-5.8,-5.8) AA8(-4.96,-5.8) AA9(-4.12,-5.86) AA10(-3.32,-5.86) AA12(-1.64,-5.86) AA13(-0.84,-5.86) AA14(0,-5.86) AA15(0.84,-5.86) AA16(1.64,-5.86) AA18(3.32,-5.86) AA19(4.12,-5.86) AA20(4.96,-5.8) AA21(5.8,-5.8) AA22(6.66,-5.8) AA23(7.5,-5.8) AA24(8.3,-5.8) AA25(9.1,-5.8) AA26(9.9,-5.8) AA27(10.7,-5.8) AB1(-10.7,-6.6) AB2(-9.9,-6.6) AB3(-9.1,-6.6) AB4(-8.3,-6.6) AB5(-7.5,-6.6) AB6(-6.6,-6.6) AB7(-5.8,-6.66) AB8(-4.96,-6.66) AB9(-4.12,-6.66) AB10(-3.32,-6.66) AB11(-2.48,-6.66) AB12(-1.64,-6.66) AB13(-0.84,-6.66) AB14(0,-6.66) AB15(0.84,-6.66) AB16(1.64,-6.66) AB17(2.48,-6.66) AB18(3.32,-6.66) AB19(4.12,-6.66) AB20(4.96,-6.66) AB21(5.8,-6.66) AB22(6.6,-6.6) AB23(7.5,-6.6) AB24(8.3,-6.6) AB25(9.1,-6.6) AB26(9.9,-6.6) AB27(10.7,-6.6) AC2(-9.9,-7.45) AC3(-9.1,-7.45) AC4(-8.3,-7.45) AC5(-7.45,-7.45) AC6(-6.6,-7.5) AC7(-5.8,-7.5) AC8(-4.96,-7.5) AC9(-4.12,-7.5) AC10(-3.32,-7.5) AC11(-2.48,-7.5) AC12(-1.64,-7.5) AC13(-0.84,-7.5) AC14(0,-7.5) AC15(0.84,-7.5) AC16(1.64,-7.5) AC17(2.48,-7.5) AC18(3.32,-7.5) AC19(4.12,-7.5) AC20(4.96,-7.5) AC21(5.8,-7.5) AC22(6.6,-7.5) AC23(7.45,-7.45) AC24(8.3,-7.45) AC25(9.1,-7.45) AC26(9.9,-7.45) AD1(-10.7,-8.3) AD2(-9.9,-8.3) AD3(-9.1,-8.3) AD4(-8.3,-8.3) AD5(-7.45,-8.3) AD6(-6.6,-8.3) AD7(-5.8,-8.3) AD8(-4.96,-8.3) AD9(-4.12,-8.3) AD10(-3.32,-8.3) AD11(-2.48,-8.3) AD12(-1.64,-8.3) AD13(-0.84,-8.3) AD14(0,-8.3) AD15(0.84,-8.3) AD16(1.64,-8.3) AD17(2.48,-8.3) AD18(3.32,-8.3) AD19(4.12,-8.3) AD20(4.96,-8.3) AD21(5.8,-8.3) AD22(6.6,-8.3) AD23(7.45,-8.3) AD24(8.3,-8.3) AD25(9.1,-8.3) AD26(9.9,-8.3) AD27(10.7,-8.3) AE1(-10.7,-9.1) AE2(-9.9,-9.1) AE3(-9.1,-9.1) AE4(-8.3,-9.1) AE5(-7.45,-9.1) AE6(-6.6,-9.1) AE7(-5.8,-9.1) AE8(-4.96,-9.1) AE9(-4.12,-9.1) AE10(-3.32,-9.1) AE11(-2.48,-9.1) AE12(-1.64,-9.1) AE13(-0.84,-9.1) AE14(0,-9.1) AE15(0.84,-9.1) AE16(1.64,-9.1) AE17(2.48,-9.1) AE18(3.32,-9.1) AE19(4.12,-9.1) AE20(4.96,-9.1) AE21(5.8,-9.1) AE22(6.6,-9.1) AE23(7.45,-9.1) AE24(8.3,-9.1) AE25(9.1,-9.1) AE26(9.9,-9.1) AE27(10.7,-9.1) AF1(-10.7,-9.9) AF2(-9.9,-9.9) AF3(-9.1,-9.9) AF4(-8.3,-9.9) AF5(-7.45,-9.9) AF6(-6.6,-9.9) AF7(-5.8,-9.9) AF8(-4.96,-9.9) AF9(-4.12,-9.9) AF10(-3.32,-9.9) AF11(-2.48,-9.9) AF12(-1.64,-9.9) AF13(-0.84,-9.9) AF14(0,-9.9) AF15(0.84,-9.9) AF16(1.64,-9.9) AF17(2.48,-9.9) AF18(3.32,-9.9) AF19(4.12,-9.9) AF20(4.96,-9.9) AF21(5.8,-9.9) AF22(6.6,-9.9) AF23(7.45,-9.9) AF24(8.3,-9.9) AF25(9.1,-9.9) AF26(9.9,-9.9) AF27(10.7,-9.9) AG2(-9.9,-10.7) AG3(-9.1,-10.7) AG4(-8.3,-10.7) AG6(-6.6,-10.7) AG7(-5.8,-10.7) AG9(-4.12,-10.7) AG10(-3.32,-10.7) AG12(-1.64,-10.7) AG13(-0.84,-10.7) AG15(0.84,-10.7) AG16(1.64,-10.7) AG18(3.32,-10.7) AG19(4.12,-10.7) AG21(5.8,-10.7) AG22(6.6,-10.7) AG24(8.3,-10.7) AG25(9.1,-10.7) AG26(9.9,-10.7) B1(-10.7,9.9) B2(-9.9,9.9) B3(-9.1,9.9) B4(-8.3,9.9) B5(-7.45,9.9) B6(-6.6,9.9) B7(-5.8,9.9) B8(-4.96,9.9) B9(-4.12,9.9) B10(-3.32,9.9) B11(-2.48,9.9) B12(-1.64,9.9) B13(-0.84,9.9) B14(0,9.9) B15(0.84,9.9) B16(1.64,9.9) B17(2.48,9.9) B18(3.32,9.9) B19(4.12,9.9) B20(4.96,9.9) B21(5.8,9.9) B22(6.6,9.9) B23(7.45,9.9) B24(8.3,9.9) B25(9.1,9.9) B26(9.9,9.9) B27(10.7,9.9) C1(-10.7,9.1) C2(-9.9,9.1) C3(-9.1,9.1) C4(-8.3,9.1) C5(-7.45,9.1) C6(-6.6,9.1) C7(-5.8,9.1) C8(-4.96,9.1) C9(-4.12,9.1) C10(-3.32,9.1) C11(-2.48,9.1) C12(-1.64,9.1) C13(-0.84,9.1) C14(0,9.1) C15(0.84,9.1) C16(1.64,9.1) C17(2.48,9.1) C18(3.32,9.1) C19(4.12,9.1) C20(4.96,9.1) C21(5.8,9.1) C22(6.6,9.1) C23(7.45,9.1) C24(8.3,9.1) C25(9.1,9.1) C26(9.9,9.1) C27(10.7,9.1) D1(-10.7,8.3) D2(-9.9,8.3) D3(-9.1,8.3) D4(-8.3,8.3) D5(-7.45,8.3) D6(-6.6,8.3) D7(-5.8,8.3) D8(-4.96,8.3) D9(-4.12,8.3) D10(-3.32,8.3) D11(-2.48,8.3) D12(-1.64,8.3) D13(-0.84,8.3) D14(0,8.3) D15(0.84,8.3) D16(1.64,8.3) D17(2.48,8.3) D18(3.32,8.3) D19(4.12,8.3) D20(4.96,8.3) D21(5.8,8.3) D22(6.6,8.3) D23(7.45,8.3) D24(8.3,8.3) D25(9.1,8.3) D26(9.9,8.3) D27(10.7,8.3) E2(-9.9,7.45) E3(-9.1,7.45) E4(-8.3,7.45) E5(-7.45,7.45) E6(-6.6,7.5) E7(-5.8,7.5) E8(-4.96,7.5) E9(-4.12,7.5) E10(-3.32,7.5) E11(-2.48,7.5) E12(-1.64,7.5) E13(-0.84,7.5) E14(0,7.5) E15(0.84,7.5) E16(1.64,7.5) E17(2.48,7.5) E18(3.32,7.5) E19(4.12,7.5) E20(4.96,7.5) E21(5.8,7.5) E22(6.6,7.5) E23(7.45,7.45) E24(8.3,7.45) E25(9.1,7.45) E26(9.9,7.45) F1(-10.7,6.6) F2(-9.9,6.6) F3(-9.1,6.6) F4(-8.3,6.6) F5(-7.5,6.6) F6(-6.6,6.6) F7(-5.8,6.66) F8(-4.96,6.66) F9(-4.12,6.66) F10(-3.32,6.66) F11(-2.48,6.66) F12(-1.64,6.66) F13(-0.84,6.66) F14(0,6.66) F15(0.84,6.66) F16(1.64,6.66) F17(2.48,6.66) F18(3.32,6.66) F19(4.12,6.66) F20(4.96,6.66) F21(5.8,6.66) F22(6.6,6.6) F23(7.5,6.6) F24(8.3,6.6) F25(9.1,6.6) F26(9.9,6.6) F27(10.7,6.6) G1(-10.7,5.8) G2(-9.9,5.8) G3(-9.1,5.8) G4(-8.3,5.8) G5(-7.5,5.8) G6(-6.66,5.8) G7(-5.8,5.8) G8(-4.96,5.8) G9(-4.12,5.86) G10(-3.32,5.86) G12(-1.64,5.86) G13(-0.84,5.86) G14(0,5.86) G15(0.84,5.86) G16(1.64,5.86) G18(3.32,5.86) G19(4.12,5.86) G20(4.96,5.8) G21(5.8,5.8) G22(6.66,5.8) G23(7.5,5.8) G24(8.3,5.8) G25(9.1,5.8) G26(9.9,5.8) G27(10.7,5.8) H2(-9.9,4.96) H3(-9.1,4.96) H4(-8.3,4.96) H5(-7.5,4.96) H6(-6.66,4.96) H22(6.66,4.96) H23(7.5,4.96) H24(8.3,4.96) H25(9.1,4.96) H26(9.9,4.96) J1(-10.7,4.12) J2(-9.9,4.12) J3(-9.1,4.12) J4(-8.3,4.12) J5(-7.5,4.12) J6(-6.66,4.12) J7(-5.86,4.12) J21(5.86,4.12) J22(6.66,4.12) J23(7.5,4.12) J24(8.3,4.12) J25(9.1,4.12) J26(9.9,4.12) J27(10.7,4.12) K1(-10.7,3.32) K2(-9.9,3.32) K3(-9.1,3.32) K4(-8.3,3.32) K5(-7.5,3.32) K6(-6.66,3.32) K7(-5.86,3.32) K21(5.86,3.32) K22(6.66,3.32) K23(7.5,3.32) K24(8.3,3.32) K25(9.1,3.32) K26(9.9,3.32) K27(10.7,3.32) L2(-9.9,2.48) L3(-9.1,2.48) L4(-8.3,2.48) L5(-7.5,2.48) L6(-6.66,2.48) L22(6.66,2.48) L23(7.5,2.48) L24(8.3,2.48) L25(9.1,2.48) L26(9.9,2.48) M1(-10.7,1.64) M2(-9.9,1.64) M3(-9.1,1.64) M4(-8.3,1.64) M5(-7.5,1.64) M6(-6.66,1.64) M7(-5.86,1.64) M21(5.86,1.64) M22(6.66,1.64) M23(7.5,1.64) M24(8.3,1.64) M25(9.1,1.64) M26(9.9,1.64) M27(10.7,1.64) N1(-10.7,0.84) N2(-9.9,0.84) N3(-9.1,0.84) N4(-8.3,0.84) N5(-7.5,0.84) N6(-6.66,0.84) N7(-5.86,0.84) N21(5.86,0.84) N22(6.66,0.84) N23(7.5,0.84) N24(8.3,0.84) N25(9.1,0.84) N26(9.9,0.84) N27(10.7,0.84) P2(-9.9,0) P3(-9.1,0) P4(-8.3,0) P5(-7.5,0) P6(-6.66,0) P22(6.66,0) P23(7.5,0) P24(8.3,0) P25(9.1,0) P26(9.9,0) R1(-10.7,-0.84) R2(-9.9,-0.84) R3(-9.1,-0.84) R4(-8.3,-0.84) R5(-7.5,-0.84) R6(-6.66,-0.84) R7(-5.86,-0.84) R21(5.86,-0.84) R22(6.66,-0.84) R23(7.5,-0.84) R24(8.3,-0.84) R25(9.1,-0.84) R26(9.9,-0.84) R27(10.7,-0.84) T1(-10.7,-1.64) T2(-9.9,-1.64) T3(-9.1,-1.64) T4(-8.3,-1.64) T5(-7.5,-1.64) T6(-6.66,-1.64) T7(-5.86,-1.64) T21(5.86,-1.64) T22(6.66,-1.64) T23(7.5,-1.64) T24(8.3,-1.64) T25(9.1,-1.64) T26(9.9,-1.64) T27(10.7,-1.64) U2(-9.9,-2.48) U3(-9.1,-2.48) U4(-8.3,-2.48) U5(-7.5,-2.48) U6(-6.66,-2.48) U22(6.66,-2.48) U23(7.5,-2.48) U24(8.3,-2.48) U25(9.1,-2.48) U26(9.9,-2.48) V1(-10.7,-3.32) V2(-9.9,-3.32) V3(-9.1,-3.32) V4(-8.3,-3.32) V5(-7.5,-3.32) V6(-6.66,-3.32) V7(-5.86,-3.32) V21(5.86,-3.32) V22(6.66,-3.32) V23(7.5,-3.32) V24(8.3,-3.32) V25(9.1,-3.32) V26(9.9,-3.32) V27(10.7,-3.32) W1(-10.7,-4.12) W2(-9.9,-4.12) W3(-9.1,-4.12) W4(-8.3,-4.12) W5(-7.5,-4.12) W6(-6.66,-4.12) W7(-5.86,-4.12) W21(5.86,-4.12) W22(6.66,-4.12) W23(7.5,-4.12) W24(8.3,-4.12) W25(9.1,-4.12) W26(9.9,-4.12) W27(10.7,-4.12) Y2(-9.9,-4.96) Y3(-9.1,-4.96) Y4(-8.3,-4.96) Y5(-7.5,-4.96) Y6(-6.66,-4.96) Y22(6.66,-4.96) Y23(7.5,-4.96) Y24(8.3,-4.96) Y25(9.1,-4.96) Y26(9.9,-4.96)
  round 0.4 smd: K10(-4,4) K11(-3,4) K12(-2,4) K13(-1,4) K14(0,4) K15(1,4) K16(2,4) K17(3,4) K18(4,4) L10(-4,3) L11(-3,3) L12(-2,3) L13(-1,3) L14(0,3) L15(1,3) L16(2,3) L17(3,3) L18(4,3) M10(-4,2) M11(-3,2) M12(-2,2) M13(-1,2) M14(0,2) M15(1,2) M16(2,2) M17(3,2) M18(4,2) N10(-4,1) N11(-3,1) N12(-2,1) N13(-1,1) N14(0,1) N15(1,1) N16(2,1) N17(3,1) N18(4,1) P10(-4,0) P11(-3,0) P12(-2,0) P13(-1,0) P14(0,0) P15(1,0) P16(2,0) P17(3,0) P18(4,0) R10(-4,-1) R11(-3,-1) R12(-2,-1) R13(-1,-1) R14(0,-1) R15(1,-1) R16(2,-1) R17(3,-1) R18(4,-1) T10(-4,-2) T11(-3,-2) T12(-2,-2) T13(-1,-2) T14(0,-2) T15(1,-2) T16(2,-2) T17(3,-2) T18(4,-2) U10(-4,-3) U11(-3,-3) U12(-2,-3) U13(-1,-3) U14(0,-3) U15(1,-3) U16(2,-3) U17(3,-3) U18(4,-3) V10(-4,-4) V11(-3,-4) V12(-2,-4) V13(-1,-4) V14(0,-4) V15(1,-4) V16(2,-4) V17(3,-4) V18(4,-4)
BGA1168-INTEL-HASWELL
  round 0.508 smd: A3(18.177,-11.314) A62(-18.722,-11.314) AW1(19.314,10.727) AW63(-19.314,10.743) AY2(18.771,11.314) AY62(-18.748,11.314) B2(18.806,-10.806) B63(-19.314,-10.722) C1(19.314,-10.177)
  round 0.381 smd: A4(17.421,-11.314) A5(16.76,-11.314) A6(15.564,-11.314) A59(-16.586,-11.314) A60(-17.412,-11.314) A61(-18.072,-11.314) AA9(14.282,0.262) AA21(7.627,0.175) AA23(6.199,0.175) AA58(-16.063,0.015) AB10(13.838,0.738) AB20(8.135,0.582) AB21(7.627,0.988) AB22(6.707,0.582) AB23(6.199,0.988) AB57(-15.743,0.666) AC9(14.282,1.215) AC20(8.135,1.394) AC22(6.707,1.394) AC58(-16.063,1.316) AD10(13.838,1.691) AD21(7.627,1.801) AD23(6.199,1.801) AD57(-15.743,1.966) AE9(14.282,2.167) AE10(13.838,2.643) AE20(8.135,2.207) AE21(7.627,2.614) AE22(6.707,2.207) AE23(6.199,2.614) AE58(-16.063,2.616) AF9(14.282,3.12) AF11(13.255,2.968) AF12(12.442,2.968) AF14(11.63,2.968) AF15(10.817,2.968) AF17(10.004,2.968) AF18(9.191,2.968) AF20(8.378,2.968) AF22(6.707,3.02) AG10(13.662,3.476) AG11(12.849,3.476) AG13(12.036,3.476) AG14(11.223,3.476) AG16(10.41,3.476) AG17(9.598,3.476) AG19(8.785,3.476) AG20(7.972,3.476) AG23(6.199,3.426) AG57(-15.743,3.267) AG58(-16.377,3.695) AH22(6.707,3.833) AH24(5.394,3.975) AH26(4.094,3.975) AH28(2.793,3.975) AH30(1.493,3.975) AH32(0.192,3.975) AH34(-1.108,3.975) AH36(-2.409,3.975) AH38(-3.709,3.975) AH40(-5.01,3.975) AH42(-6.31,3.975) AH44(-7.611,3.975) AH46(-8.911,3.975) AH49(-10.212,3.975) AH51(-11.512,3.975) AH53(-12.813,3.975) AH55(-14.113,3.975) AH57(-15.413,3.975) AJ23(6.199,4.239) AJ25(4.744,4.3) AJ27(3.443,4.3) AJ29(2.143,4.3) AJ31(0.843,4.3) AJ33(-0.458,4.3) AJ35(-1.758,4.3) AJ37(-3.059,4.3) AJ39(-4.359,4.3) AJ41(-5.66,4.3) AJ43(-6.96,4.3) AJ45(-8.261,4.3) AJ47(-9.561,4.3) AJ50(-10.862,4.3) AJ52(-12.162,4.3) AJ54(-13.463,4.3) AJ56(-14.763,4.3) AJ58(-16.064,4.3) AT1(19.314,8.683) AT63(-19.314,8.533) AU1(19.314,9.343) AU63(-19.314,9.359) AV1(19.314,10.004) AV2(18.654,9.993) AV62(-18.664,10.004) AV63(-19.314,10.019) AW2(18.654,10.654) AW3(17.993,10.654) AW61(-18.014,10.664) AW62(-18.664,10.664) AY3(18.047,11.314) AY4(17.387,11.314) AY5(16.726,11.314) AY59(-16.774,11.314) AY60(-17.434,11.314) AY61(-18.095,11.314) B3(18.056,-10.664) B61(-18.001,-10.654) B62(-18.664,-10.59) C2(18.664,-10.056) C62(-18.664,-9.93) C63(-19.314,-9.998) D1(19.314,-9.453) D63(-19.314,-9.338) E1(19.314,-8.792) E23(5.981,-8.713) E25(4.6,-8.713) E27(3.474,-8.713) E29(2.093,-8.713) E31(0.966,-8.713) E33(-0.415,-8.713) E35(-1.541,-8.713) E37(-2.922,-8.713) E39(-4.049,-8.713) E41(-5.43,-8.713) E43(-6.556,-8.713) E45(-7.937,-8.713) E47(-9.064,-8.713) E49(-10.444,-8.713) E51(-11.571,-8.713) E53(-12.952,-8.713) E55(-14.079,-8.713) E57(-15.459,-8.713) E63(-19.314,-8.667) F1(19.314,-7.878) F22(6.597,-8.256) F24(5.291,-8.188) F26(4.037,-8.188) F28(2.783,-8.188) F30(1.53,-8.188) F32(0.276,-8.188) F34(-0.978,-8.188) F36(-2.232,-8.188) F38(-3.485,-8.188) F40(-4.739,-8.188) F42(-5.993,-8.188) F44(-7.247,-8.188) F46(-8.5,-8.188) F48(-9.754,-8.188) F50(-11.008,-8.188) F52(-12.262,-8.188) F54(-13.515,-8.188) F56(-14.769,-8.188) F58(-16.063,-8.188) G22(6.707,-7.546) G23(5.981,-7.863) G25(4.6,-7.863) G27(3.474,-7.863) G29(2.093,-7.863) G31(0.966,-7.863) G33(-0.415,-7.863) G35(-1.541,-7.863) G37(-2.922,-7.863) G39(-4.049,-7.863) G41(-5.43,-7.863) G43(-6.556,-7.863) G45(-7.937,-7.863) G47(-9.064,-7.863) G49(-10.444,-7.863) G51(-11.571,-7.863) G53(-12.952,-7.863) G55(-14.079,-7.863) G57(-15.459,-7.863) H22(6.707,-6.734) H23(6.199,-7.14) H57(-15.743,-7.213) J22(6.707,-5.921) J23(6.199,-6.327) J58(-16.063,-6.487) K9(14.282,-5.453) K10(13.379,-5.614) K12(12.426,-5.614) K14(11.474,-5.614) K16(10.521,-5.614) K18(9.569,-5.614) K19(8.616,-5.614) K21(7.664,-5.614) K23(6.199,-5.514) K57(-15.743,-5.837) L10(13.838,-4.977) L11(12.902,-5.17) L13(11.95,-5.17) L15(10.997,-5.17) L17(10.045,-5.17) L18(9.092,-5.17) L20(8.135,-5.108) L22(6.707,-5.108) L58(-16.063,-5.186) M9(14.282,-4.5) M20(8.135,-4.295) M21(7.627,-4.702) M22(6.707,-4.295) M23(6.199,-4.702) M57(-15.743,-4.536) N10(13.838,-4.024) N21(7.627,-3.889) N23(6.199,-3.889) N58(-16.063,-3.886) P9(14.282,-3.548) P20(8.135,-3.482) P22(6.707,-3.482) P57(-15.743,-3.236) R10(13.838,-3.072) R20(8.135,-2.67) R21(7.627,-3.076) R22(6.707,-2.67) R23(6.199,-3.076) T9(14.282,-2.595) T21(7.627,-2.263) T23(6.199,-2.263) T58(-16.063,-2.585) U9(14.282,-1.643) U10(13.838,-2.119) U20(8.135,-1.857) U22(6.707,-1.857) U57(-15.743,-1.935) V10(13.838,-1.167) V21(7.627,-1.45) V23(6.199,-1.45) V58(-16.063,-1.285) W9(14.282,-0.69) W20(8.135,-1.044) W21(7.627,-0.638) W22(6.707,-1.044) W23(6.199,-0.638) W57(-15.743,-0.635) Y10(13.838,-0.214) Y20(8.135,-0.231) Y22(6.707,-0.231)
  round 0.305 smd: A8(14.776,-11.314) A9(13.862,-11.314) A11(12.948,-11.314) A12(12.198,-11.314) A14(11.284,-11.314) A15(10.37,-11.314) A17(9.62,-11.314) A18(8.706,-11.314) A20(7.791,-11.314) A21(7.042,-11.314) A23(6.128,-11.314) A24(5.291,-10.989) A25(4.6,-11.314) A27(3.474,-11.314) A28(2.783,-10.989) A29(2.093,-11.314) A31(0.966,-11.314) A32(0.276,-10.989) A33(-0.415,-11.314) A35(-1.541,-11.314) A36(-2.232,-10.989) A37(-2.922,-11.314) A39(-4.049,-11.314) A40(-4.739,-10.989) A41(-5.43,-11.314) A43(-6.556,-11.314) A44(-7.247,-10.989) A45(-7.937,-11.314) A47(-9.064,-11.314) A48(-9.754,-10.989) A49(-10.444,-11.314) A51(-11.571,-11.314) A52(-12.262,-10.989) A53(-12.952,-11.314) A55(-14.079,-11.314) A56(-14.769,-10.989) A57(-15.459,-11.314) AA1(19.314,0.402) AA2(18.664,0.402) AA3(18.014,0.364) AA4(17.363,0.364) AA59(-16.713,0.324) AA60(-17.363,0.324) AA61(-18.014,0.324) AA62(-18.664,0.362) AA63(-19.314,0.362) AB5(16.678,0.738) AB6(16.027,0.738) AB7(15.377,0.738) AB8(14.727,0.738) AC1(19.314,1.152) AC2(18.664,1.152) AC3(18.014,1.19) AC4(17.363,1.19) AC59(-16.713,1.15) AC60(-17.363,1.15) AC61(-18.014,1.15) AC62(-18.664,1.112) AC63(-19.314,1.112) AD1(19.314,1.901) AD2(18.664,1.901) AD3(18.014,1.863) AD4(17.363,1.863) AD5(16.678,1.691) AD6(16.027,1.691) AD7(15.377,1.691) AD8(14.727,1.691) AD59(-16.713,1.823) AD60(-17.363,1.823) AD61(-18.014,1.823) AD62(-18.664,1.861) AD63(-19.314,1.861) AE5(16.678,2.643) AE6(16.027,2.643) AE7(15.377,2.643) AE8(14.727,2.643) AE59(-16.713,2.648) AE60(-17.363,2.648) AE61(-18.014,2.648) AE62(-18.664,2.61) AE63(-19.314,2.61) AF1(19.314,2.65) AF2(18.664,2.65) AF3(18.014,2.688) AF4(17.363,2.688) AG1(19.314,3.4) AG2(18.664,3.4) AG3(18.014,3.361) AG4(17.363,3.361) AG5(16.678,3.596) AG6(16.027,3.596) AG7(15.377,3.596) AG8(14.727,3.596) AG21(7.359,3.807) AG60(-17.038,3.288) AG61(-17.689,3.288) AG62(-18.339,3.288) AG63(-18.989,3.288) AH1(19.314,4.149) AH2(18.664,4.149) AH3(18.014,4.187) AH4(17.363,4.187) AH10(13.662,4.162) AH11(12.849,4.162) AH13(12.036,4.162) AH14(11.223,4.162) AH16(10.41,4.162) AH17(9.598,4.162) AH19(8.785,4.162) AH20(7.972,4.162) AH60(-17.363,3.964) AH61(-18.014,3.964) AH62(-18.664,3.964) AH63(-19.314,3.964) AJ5(16.678,4.548) AJ6(16.027,4.548) AJ7(15.377,4.548) AJ8(14.727,4.548) AJ10(13.662,4.812) AJ11(12.849,4.812) AJ13(12.036,4.812) AJ14(11.223,4.812) AJ60(-17.038,4.64) AJ61(-17.689,4.64) AJ62(-18.339,4.64) AJ63(-18.989,4.64) AK1(19.314,4.898) AK2(18.664,4.898) AK3(18.014,4.86) AK4(17.363,4.86) AK8(15.011,5.137) AK18(9.466,4.952) AK20(8.513,4.952) AK21(7.561,4.952) AK60(-17.363,5.209) AK61(-18.014,5.209) AK62(-18.664,5.315) AK63(-19.314,5.315) AL1(19.314,5.647) AL2(18.664,5.647) AL3(18.014,5.686) AL4(17.363,5.686) AL5(16.413,5.462) AL7(15.575,5.462) AL8(15.011,5.787) AL10(13.657,5.462) AL11(13.093,5.787) AL13(11.738,5.462) AL15(11.174,5.787) AL17(10.092,5.268) AL18(9.466,5.602) AL20(8.513,5.602) AL21(7.561,5.602) AL22(6.608,5.602) AL23(5.786,5.602) AL25(4.81,5.602) AL26(3.858,5.602) AL28(2.905,5.602) AL29(1.953,5.602) AL31(1.054,5.277) AL32(0.49,5.602) AL33(-0.412,5.602) AL35(-1.415,5.602) AL36(-2.266,5.602) AL38(-3.32,5.602) AL39(-4.228,5.277) AL40(-4.817,5.602) AL42(-5.63,5.602) AL43(-6.582,5.602) AL45(-7.56,5.602) AL46(-8.487,5.602) AL48(-9.542,5.602) AL49(-10.443,5.602) AL51(-11.447,5.602) AL52(-12.269,5.602) AL54(-13.295,5.602) AL55(-14.248,5.602) AL57(-15.195,5.602) AL58(-16.094,5.602) AL60(-17.038,5.855) AL61(-17.689,5.855) AM1(19.314,6.397) AM2(18.664,6.397) AM3(18.014,6.359) AM4(17.363,6.359) AM5(16.413,6.112) AM7(15.575,6.112) AM8(15.011,6.437) AM10(13.657,6.112) AM11(13.093,6.437) AM13(11.738,6.112) AM15(11.174,6.437) AM17(10.092,5.919) AM18(9.466,6.252) AM20(8.513,6.252) AM21(7.561,6.252) AM22(6.608,6.252) AM23(5.786,6.252) AM25(4.81,6.252) AM26(3.858,6.252) AM28(2.905,6.252) AM29(1.953,6.252) AM31(1.054,5.927) AM32(0.49,6.252) AM33(-0.412,6.252) AM35(-1.415,6.252) AM36(-2.266,6.252) AM38(-3.32,6.252) AM40(-4.817,6.252) AM42(-5.63,6.252) AM43(-6.582,6.252) AM45(-7.56,6.252) AM46(-8.487,6.252) AM48(-9.542,6.252) AM49(-10.443,6.252) AM51(-11.447,6.252) AM52(-12.269,6.252) AM54(-13.295,6.252) AM55(-14.248,6.252) AM57(-15.195,6.252) AM58(-16.094,6.252) AM60(-17.363,6.501) AM61(-18.014,6.501) AM62(-18.664,6.395) AM63(-19.314,6.395) AN1(19.314,7.146) AN2(18.664,7.146) AN3(18.014,7.184) AN4(17.363,7.184) AN5(16.413,6.762) AN7(15.575,6.762) AN8(15.011,7.088) AN10(13.657,6.762) AN11(13.093,7.088) AN13(11.738,6.762) AN15(11.174,7.088) AN17(10.092,6.569) AN18(9.466,6.903) AN20(8.513,6.903) AN21(7.561,6.903) AN22(6.608,6.903) AN23(5.786,6.903) AN25(4.81,6.903) AN26(3.858,6.903) AN28(2.905,6.903) AN29(1.953,6.903) AN31(1.054,6.578) AN32(0.49,6.903) AN33(-0.412,6.903) AN35(-1.415,6.903) AN36(-2.266,6.903) AN38(-3.32,6.903) AN39(-4.228,6.578) AN40(-4.817,6.903) AN42(-5.63,6.903) AN43(-6.582,6.903) AN45(-7.56,6.903) AN46(-8.487,6.903) AN48(-9.542,6.903) AN49(-10.443,6.903) AN51(-11.447,6.903) AN52(-12.269,6.903) AN54(-13.295,6.903) AN55(-14.248,6.903) AN57(-15.195,6.903) AN58(-16.094,6.903) AN60(-17.038,7.07) AN61(-17.689,7.07) AN62(-18.339,7.07) AN63(-18.989,7.07) AP1(19.314,7.895) AP2(18.664,7.895) AP3(18.014,7.857) AP4(17.363,7.857) AP5(16.413,7.413) AP7(15.575,7.413) AP8(15.011,7.738) AP10(13.657,7.413) AP11(13.093,7.738) AP13(11.738,7.413) AP15(11.174,7.738) AP17(10.092,7.219) AP18(9.466,7.553) AP20(8.513,7.553) AP21(7.561,7.553) AP22(6.608,7.553) AP23(5.786,7.553) AP25(4.81,7.553) AP26(3.858,7.553) AP28(2.905,7.553) AP29(1.953,7.553) AP31(1.054,7.228) AP32(0.49,7.553) AP33(-0.412,7.553) AP35(-1.415,7.553) AP36(-2.266,7.553) AP38(-3.32,7.553) AP39(-4.228,7.228) AP40(-4.817,7.553) AP42(-5.63,7.553) AP43(-6.582,7.553) AP45(-7.56,7.553) AP46(-8.487,7.553) AP48(-9.542,7.553) AP49(-10.443,7.553) AP51(-11.447,7.553) AP52(-12.269,7.553) AP54(-13.295,7.553) AP55(-14.248,7.553) AP57(-15.195,7.553) AP58(-16.094,7.553) AP60(-17.363,7.746) AP61(-18.014,7.746) AP62(-18.664,7.746) AP63(-19.314,7.746) AR5(16.413,8.063) AR7(15.575,8.063) AR8(15.011,8.388) AR10(13.657,8.063) AR11(13.093,8.388) AR13(11.738,8.063) AR15(11.174,8.388) AR17(10.092,7.869) AR18(9.466,8.203) AR20(8.513,8.203) AR21(7.561,8.203) AR22(6.608,8.203) AR23(5.786,8.203) AR25(4.81,8.203) AR26(3.858,8.203) AR28(2.905,8.203) AR29(1.953,8.203) AR31(1.054,7.878) AR32(0.49,8.203) AR33(-0.412,8.203) AR35(-1.415,8.203) AR36(-2.266,8.203) AR38(-3.32,8.203) AR39(-4.228,7.878) AR40(-4.817,8.203) AR42(-5.63,8.203) AR43(-6.582,8.203) AR45(-7.56,8.203) AR46(-8.487,8.203) AR48(-9.542,8.203) AR49(-10.443,8.203) AR51(-11.447,8.203) AR52(-12.269,8.203) AR54(-13.295,8.203) AR55(-14.248,8.203) AR57(-15.195,8.203) AR58(-16.094,8.203) AT2(18.664,8.645) AT3(18.014,8.683) AT4(17.363,8.683) AT5(16.413,8.713) AT7(15.575,8.713) AT10(13.657,8.713) AT13(11.738,8.713) AT35(-1.122,8.905) AT37(-2.697,8.905) AT40(-4.272,8.905) AT42(-5.847,8.905) AT43(-7.422,8.905) AT46(-8.996,8.905) AT49(-10.597,8.933) AT61(-17.689,8.32) AT62(-18.498,8.376) AU2(18.659,9.333) AU3(17.999,9.333) AU4(17.338,9.333) AU6(15.977,9.363) AU7(15.151,9.363) AU8(14.478,9.363) AU10(13.653,9.363) AU11(12.98,9.363) AU12(12.154,9.363) AU14(11.481,9.363) AU15(10.656,9.363) AU16(10.092,9.038) AU17(9.454,9.363) AU18(8.778,9.038) AU19(8.21,9.363) AU20(7.563,9.038) AU21(6.917,9.363) AU22(6.348,9.038) AU23(5.672,9.363) AU24(4.996,9.038) AU25(4.321,9.363) AU26(3.645,9.038) AU27(3.076,9.363) AU28(2.43,9.038) AU29(1.783,9.363) AU30(1.214,9.038) AU31(0.539,9.363) AU33(-0.058,9.016) AU34(-0.66,9.363) AU35(-1.585,9.363) AU36(-2.235,9.363) AU37(-3.16,9.363) AU39(-3.81,9.363) AU40(-4.734,9.363) AU41(-5.385,9.363) AU42(-6.309,9.363) AU43(-6.959,9.363) AU44(-7.884,9.363) AU46(-8.534,9.363) AU47(-9.459,9.363) AU49(-10.109,9.363) AU50(-11.086,9.363) AU51(-11.666,9.038) AU52(-12.342,9.363) AU53(-13.017,9.038) AU54(-13.586,9.363) AU55(-14.233,9.038) AU56(-14.879,9.363) AU57(-15.448,9.038) AU58(-16.124,9.363) AU59(-16.688,9.038) AU60(-17.251,9.363) AU61(-17.963,9.087) AU62(-18.664,9.349) AV3(17.993,9.993) AV4(17.338,9.993) AV5(16.65,10.014) AV6(15.977,10.014) AV7(15.151,10.014) AV8(14.478,10.014) AV10(13.653,10.014) AV11(12.98,10.014) AV12(12.154,10.014) AV14(11.481,10.014) AV15(10.656,10.014) AV16(10.092,9.689) AV17(9.454,10.014) AV18(8.778,9.689) AV19(8.21,10.014) AV20(7.563,9.689) AV21(6.917,10.014) AV22(6.348,9.689) AV23(5.672,10.014) AV24(4.996,9.689) AV25(4.321,10.014) AV26(3.645,9.689) AV27(3.076,10.014) AV28(2.43,9.689) AV29(1.783,10.014) AV30(1.214,9.689) AV31(0.539,10.014) AV33(-0.086,9.689) AV34(-0.71,10.014) AV35(-1.535,10.014) AV36(-2.284,10.014) AV37(-3.11,10.014) AV39(-3.859,10.014) AV40(-4.685,10.014) AV41(-5.434,10.014) AV42(-6.26,10.014) AV43(-7.009,10.014) AV44(-7.834,10.014) AV46(-8.584,10.014) AV47(-9.409,10.014) AV49(-10.158,10.014) AV50(-10.984,10.014) AV51(-11.666,9.689) AV52(-12.342,10.014) AV53(-13.017,9.689) AV54(-13.586,10.014) AV55(-14.233,9.689) AV56(-14.879,10.014) AV57(-15.448,9.689) AV58(-16.124,10.014) AV59(-16.688,9.689) AV60(-17.251,10.014) AV61(-17.988,9.737) AW4(17.338,10.654) AW5(16.688,10.664) AW6(15.939,10.664) AW7(15.189,10.664) AW8(14.44,10.664) AW10(13.691,10.664) AW11(12.942,10.664) AW12(12.192,10.664) AW14(11.443,10.664) AW15(10.694,10.664) AW16(10.092,10.339) AW17(9.454,10.664) AW18(8.778,10.339) AW19(8.103,10.664) AW21(7.023,10.664) AW22(6.348,10.339) AW23(5.672,10.664) AW24(4.996,10.339) AW25(4.321,10.664) AW26(3.645,10.339) AW27(2.97,10.664) AW29(1.89,10.664) AW30(1.214,10.339) AW31(0.539,10.664) AW33(-0.137,10.339) AW34(-0.71,10.664) AW35(-1.535,10.664) AW36(-2.284,10.664) AW37(-3.11,10.664) AW39(-3.859,10.664) AW40(-4.685,10.664) AW41(-5.434,10.664) AW42(-6.26,10.664) AW43(-7.009,10.664) AW44(-7.834,10.664) AW46(-8.584,10.664) AW47(-9.409,10.664) AW49(-10.158,10.664) AW50(-10.984,10.664) AW51(-11.666,10.339) AW52(-12.342,10.664) AW53(-13.017,10.339) AW54(-13.693,10.664) AW56(-14.772,10.664) AW57(-15.448,10.339) AW58(-16.124,10.664) AW59(-16.688,10.339) AW60(-17.251,10.664) AY6(15.939,11.314) AY7(15.189,11.314) AY8(14.44,11.314) AY10(13.691,11.314) AY11(12.942,11.314) AY12(12.192,11.314) AY14(11.443,11.314) AY15(10.694,11.314) AY16(10.13,10.989) AY17(9.454,11.314) AY18(8.778,10.989) AY19(8.103,11.314) AY21(7.023,11.314) AY22(6.348,10.989) AY23(5.672,11.314) AY24(4.996,10.989) AY25(4.321,11.314) AY26(3.645,10.989) AY27(2.97,11.314) AY29(1.89,11.314) AY30(1.214,10.989) AY31(0.539,11.314) AY33(-0.137,10.989) AY34(-0.71,11.314) AY35(-1.535,11.314) AY36(-2.284,11.314) AY37(-3.11,11.314) AY39(-3.859,11.314) AY40(-4.685,11.314) AY41(-5.434,11.314) AY42(-6.26,11.314) AY43(-7.009,11.314) AY44(-7.834,11.314) AY46(-8.584,11.314) AY47(-9.409,11.314) AY49(-10.158,11.314) AY50(-10.984,11.314) AY51(-11.666,10.989) AY52(-12.342,11.314) AY53(-13.017,10.989) AY54(-13.693,11.314) AY56(-14.772,11.314) AY57(-15.448,10.989) AY58(-16.124,11.314) B4(17.393,-10.664) B5(16.176,-10.672) B6(15.196,-10.672) B8(14.423,-10.672) B9(13.598,-10.672) B11(12.617,-10.672) B12(11.845,-10.672) B14(11.02,-10.672) B15(10.039,-10.672) B17(9.267,-10.672) B18(8.442,-10.672) B20(7.461,-10.672) B21(7.042,-10.118) B22(6.689,-10.672) B23(5.864,-10.672) B24(5.291,-10.339) B25(4.6,-10.664) B26(4.037,-10.339) B27(3.474,-10.664) B28(2.783,-10.339) B29(2.093,-10.664) B30(1.53,-10.339) B31(0.966,-10.664) B32(0.276,-10.339) B33(-0.415,-10.664) B34(-0.978,-10.339) B35(-1.541,-10.664) B36(-2.232,-10.339) B37(-2.922,-10.664) B38(-3.485,-10.339) B39(-4.049,-10.664) B40(-4.739,-10.339) B41(-5.43,-10.664) B42(-5.993,-10.339) B43(-6.556,-10.664) B44(-7.247,-10.339) B45(-7.937,-10.664) B46(-8.5,-10.339) B47(-9.064,-10.664) B48(-9.754,-10.339) B49(-10.444,-10.664) B50(-11.008,-10.339) B51(-11.571,-10.664) B52(-12.262,-10.339) B53(-12.952,-10.664) B54(-13.515,-10.339) B55(-14.079,-10.664) B56(-14.769,-10.339) B57(-15.459,-10.664) B58(-16.023,-10.339) B59(-16.586,-10.664) B60(-17.351,-10.654) C3(18.012,-10.012) C4(17.196,-10.042) C5(16.542,-10.118) C6(15.538,-10.118) C8(14.776,-10.118) C9(13.964,-10.118) C11(12.96,-10.118) C12(12.198,-10.118) C14(11.386,-10.118) C15(10.382,-10.118) C17(9.62,-10.118) C18(8.807,-10.118) C20(7.804,-10.118) C21(7.423,-9.529) C22(6.636,-9.529) C23(6.229,-10.118) C24(5.263,-9.282) C25(4.6,-10.014) C26(4.037,-9.689) C27(3.474,-10.014) C28(2.756,-9.282) C29(2.093,-10.014) C30(1.53,-9.689) C31(0.966,-10.014) C32(0.248,-9.282) C33(-0.415,-10.014) C34(-0.978,-9.689) C35(-1.541,-10.014) C36(-2.259,-9.282) C37(-2.922,-10.014) C38(-3.485,-9.689) C39(-4.049,-10.014) C40(-4.767,-9.282) C41(-5.43,-10.014) C42(-5.993,-9.689) C43(-6.556,-10.014) C44(-7.274,-9.282) C45(-7.937,-10.014) C46(-8.5,-9.689) C47(-9.064,-10.014) C48(-9.756,-9.282) C49(-10.444,-10.014) C50(-11.008,-9.689) C51(-11.571,-10.014) C52(-12.264,-9.323) C53(-12.952,-10.014) C54(-13.515,-9.689) C55(-14.079,-10.014) C56(-14.771,-9.323) C57(-15.459,-10.014) C58(-16.023,-9.689) C59(-16.586,-10.014) C61(-17.689,-10.077) D2(18.664,-9.24) D3(18.014,-9.278) D5(16.636,-9.472) D6(15.945,-9.529) D8(15.157,-9.529) D9(14.37,-9.529) D11(13.462,-9.529) D12(12.579,-9.529) D14(11.792,-9.529) D15(10.884,-9.529) D17(10.001,-9.529) D18(9.214,-9.529) D20(8.306,-9.529) D21(7.079,-8.891) D23(5.937,-9.529) D25(4.6,-9.363) D26(4.037,-9.038) D27(3.474,-9.363) D29(2.093,-9.363) D30(1.53,-9.038) D31(0.966,-9.363) D33(-0.415,-9.363) D34(-0.978,-9.038) D35(-1.541,-9.363) D37(-2.922,-9.363) D38(-3.485,-9.038) D39(-4.049,-9.363) D41(-5.43,-9.363) D42(-5.993,-9.038) D43(-6.556,-9.363) D45(-7.937,-9.363) D46(-8.5,-9.038) D47(-9.064,-9.363) D49(-10.444,-9.363) D50(-11.008,-9.038) D51(-11.571,-9.363) D53(-12.952,-9.363) D54(-13.515,-9.038) D55(-14.079,-9.363) D57(-15.459,-9.363) D58(-16.023,-9.038) D59(-16.586,-9.363) D60(-17.363,-9.513) D61(-18.014,-9.513) D62(-18.664,-9.28) E2(18.664,-8.589) E3(18.014,-8.627) E4(17.363,-8.627) E5(16.712,-8.695) E6(15.76,-8.695) E8(14.807,-8.695) E10(13.855,-8.695) E11(12.902,-8.695) E13(11.95,-8.695) E15(10.997,-8.695) E17(10.045,-8.695) E18(9.092,-8.695) E20(8.14,-8.695) E59(-16.713,-8.667) E60(-17.363,-8.667) E61(-18.014,-8.667) E62(-18.664,-8.629) F2(18.664,-7.84) F3(18.014,-7.802) F4(17.363,-7.802) F5(16.712,-8.045) F6(15.76,-8.045) F8(14.807,-8.045) F10(13.855,-8.045) F11(12.902,-8.045) F13(11.95,-8.045) F15(10.997,-8.045) F17(10.045,-8.045) F18(9.092,-8.045) F20(8.14,-8.045) F59(-16.713,-7.842) F60(-17.363,-7.842) F61(-18.014,-7.842) F62(-18.664,-7.88) F63(-19.314,-7.88) G1(19.314,-7.091) G2(18.664,-7.091) G3(18.014,-7.129) G4(17.363,-7.129) G5(16.712,-7.395) G6(15.76,-7.395) G8(14.807,-7.395) G10(13.855,-7.395) G11(12.902,-7.395) G13(11.95,-7.395) G15(10.997,-7.395) G17(10.045,-7.395) G18(9.092,-7.395) G20(8.14,-7.395) H5(16.712,-6.745) H6(15.76,-6.745) H8(14.807,-6.745) H10(13.855,-6.745) H11(12.902,-6.745) H13(11.95,-6.745) H15(10.997,-6.745) H17(10.045,-6.745) H18(9.092,-6.745) H20(8.14,-6.745) H59(-16.713,-7.169) H60(-17.363,-7.169) H61(-18.014,-7.169) H62(-18.664,-7.131) H63(-19.314,-7.131) J1(19.314,-6.341) J2(18.664,-6.341) J3(18.014,-6.303) J4(17.363,-6.303) J5(16.687,-6.094) J6(15.747,-6.094) J8(14.807,-6.094) J10(13.855,-6.094) J11(12.902,-6.094) J13(11.95,-6.094) J15(10.997,-6.094) J17(10.045,-6.094) J18(9.092,-6.094) J20(8.14,-6.094) J21(7.219,-6.328) J59(-16.713,-6.343) J60(-17.363,-6.343) J61(-18.014,-6.343) J62(-18.664,-6.381) J63(-19.314,-6.381) K1(19.314,-5.592) K2(18.664,-5.592) K3(18.014,-5.63) K4(17.363,-5.63) K59(-16.713,-5.67) K60(-17.363,-5.67) K61(-18.014,-5.67) K62(-18.664,-5.632) K63(-19.314,-5.632) L1(19.314,-4.843) L2(18.664,-4.843) L3(18.014,-4.805) L4(17.363,-4.805) L5(16.678,-4.977) L6(16.027,-4.977) L7(15.377,-4.977) L8(14.727,-4.977) L59(-16.713,-4.845) L60(-17.363,-4.845) L61(-18.014,-4.845) L62(-18.664,-4.883) L63(-19.314,-4.883) N1(19.314,-4.093) N2(18.664,-4.093) N3(18.014,-4.132) N4(17.363,-4.132) N5(16.678,-4.024) N6(16.027,-4.024) N7(15.377,-4.024) N8(14.727,-4.024) N59(-16.713,-4.172) N60(-17.363,-4.172) N61(-18.014,-4.172) N62(-18.664,-4.134) N63(-19.314,-4.134) P1(19.314,-3.344) P2(18.664,-3.344) P3(18.014,-3.306) P4(17.363,-3.306) P59(-16.713,-3.346) P60(-17.363,-3.346) P61(-18.014,-3.346) P62(-18.664,-3.384) P63(-19.314,-3.384) R5(16.678,-3.072) R6(16.027,-3.072) R7(15.377,-3.072) R8(14.727,-3.072) T1(19.314,-2.595) T2(18.664,-2.595) T3(18.014,-2.633) T4(17.363,-2.633) T59(-16.713,-2.673) T60(-17.363,-2.673) T61(-18.014,-2.673) T62(-18.664,-2.635) T63(-19.314,-2.635) U1(19.314,-1.846) U2(18.664,-1.846) U3(18.014,-1.807) U4(17.363,-1.807) U5(16.678,-2.119) U6(16.027,-2.119) U7(15.377,-2.119) U8(14.727,-2.119) U59(-16.713,-1.848) U60(-17.363,-1.848) U61(-18.014,-1.848) U62(-18.664,-1.886) U63(-19.314,-1.886) V1(19.314,-1.096) V2(18.664,-1.096) V3(18.014,-1.134) V4(17.363,-1.134) V5(16.678,-1.167) V6(16.027,-1.167) V7(15.377,-1.167) V8(14.727,-1.167) V59(-16.713,-1.174) V60(-17.363,-1.174) V61(-18.014,-1.174) V62(-18.664,-1.136) V63(-19.314,-1.136) Y1(19.314,-0.347) Y2(18.664,-0.347) Y3(18.014,-0.309) Y4(17.363,-0.309) Y5(16.678,-0.214) Y6(16.027,-0.214) Y7(15.377,-0.214) Y8(14.727,-0.214) Y59(-16.713,-0.349) Y60(-17.363,-0.349) Y61(-18.014,-0.349) Y62(-18.664,-0.387) Y63(-19.314,-0.387)
  round 0.33 smd: AK22(6.659,4.952) AK23(5.786,4.952) AK25(4.81,4.952) AK26(3.858,4.952) AK28(2.905,4.952) AK29(2.004,4.952) AK32(0.49,4.952) AK33(-0.412,4.952) AK35(-1.415,4.952) AK36(-2.266,4.952) AK38(-3.295,4.952) AK40(-4.792,4.952) AK42(-5.63,4.952) AK43(-6.582,4.952) AK45(-7.56,4.952) AK46(-8.462,4.952) AK48(-9.516,4.952) AK49(-10.418,4.952) AK51(-11.421,4.952) AK52(-12.269,4.952) AK54(-13.295,4.952) AK55(-14.248,4.952) AK57(-15.195,4.952) AK58(-16.094,4.952)
